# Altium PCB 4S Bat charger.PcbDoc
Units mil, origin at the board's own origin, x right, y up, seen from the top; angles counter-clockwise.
Board outline 3472.44 x 2830.71 mil, 2 copper layers (Top Layer, Bottom Layer); 157 components, 75 nets, 480 pads, 93 vias.
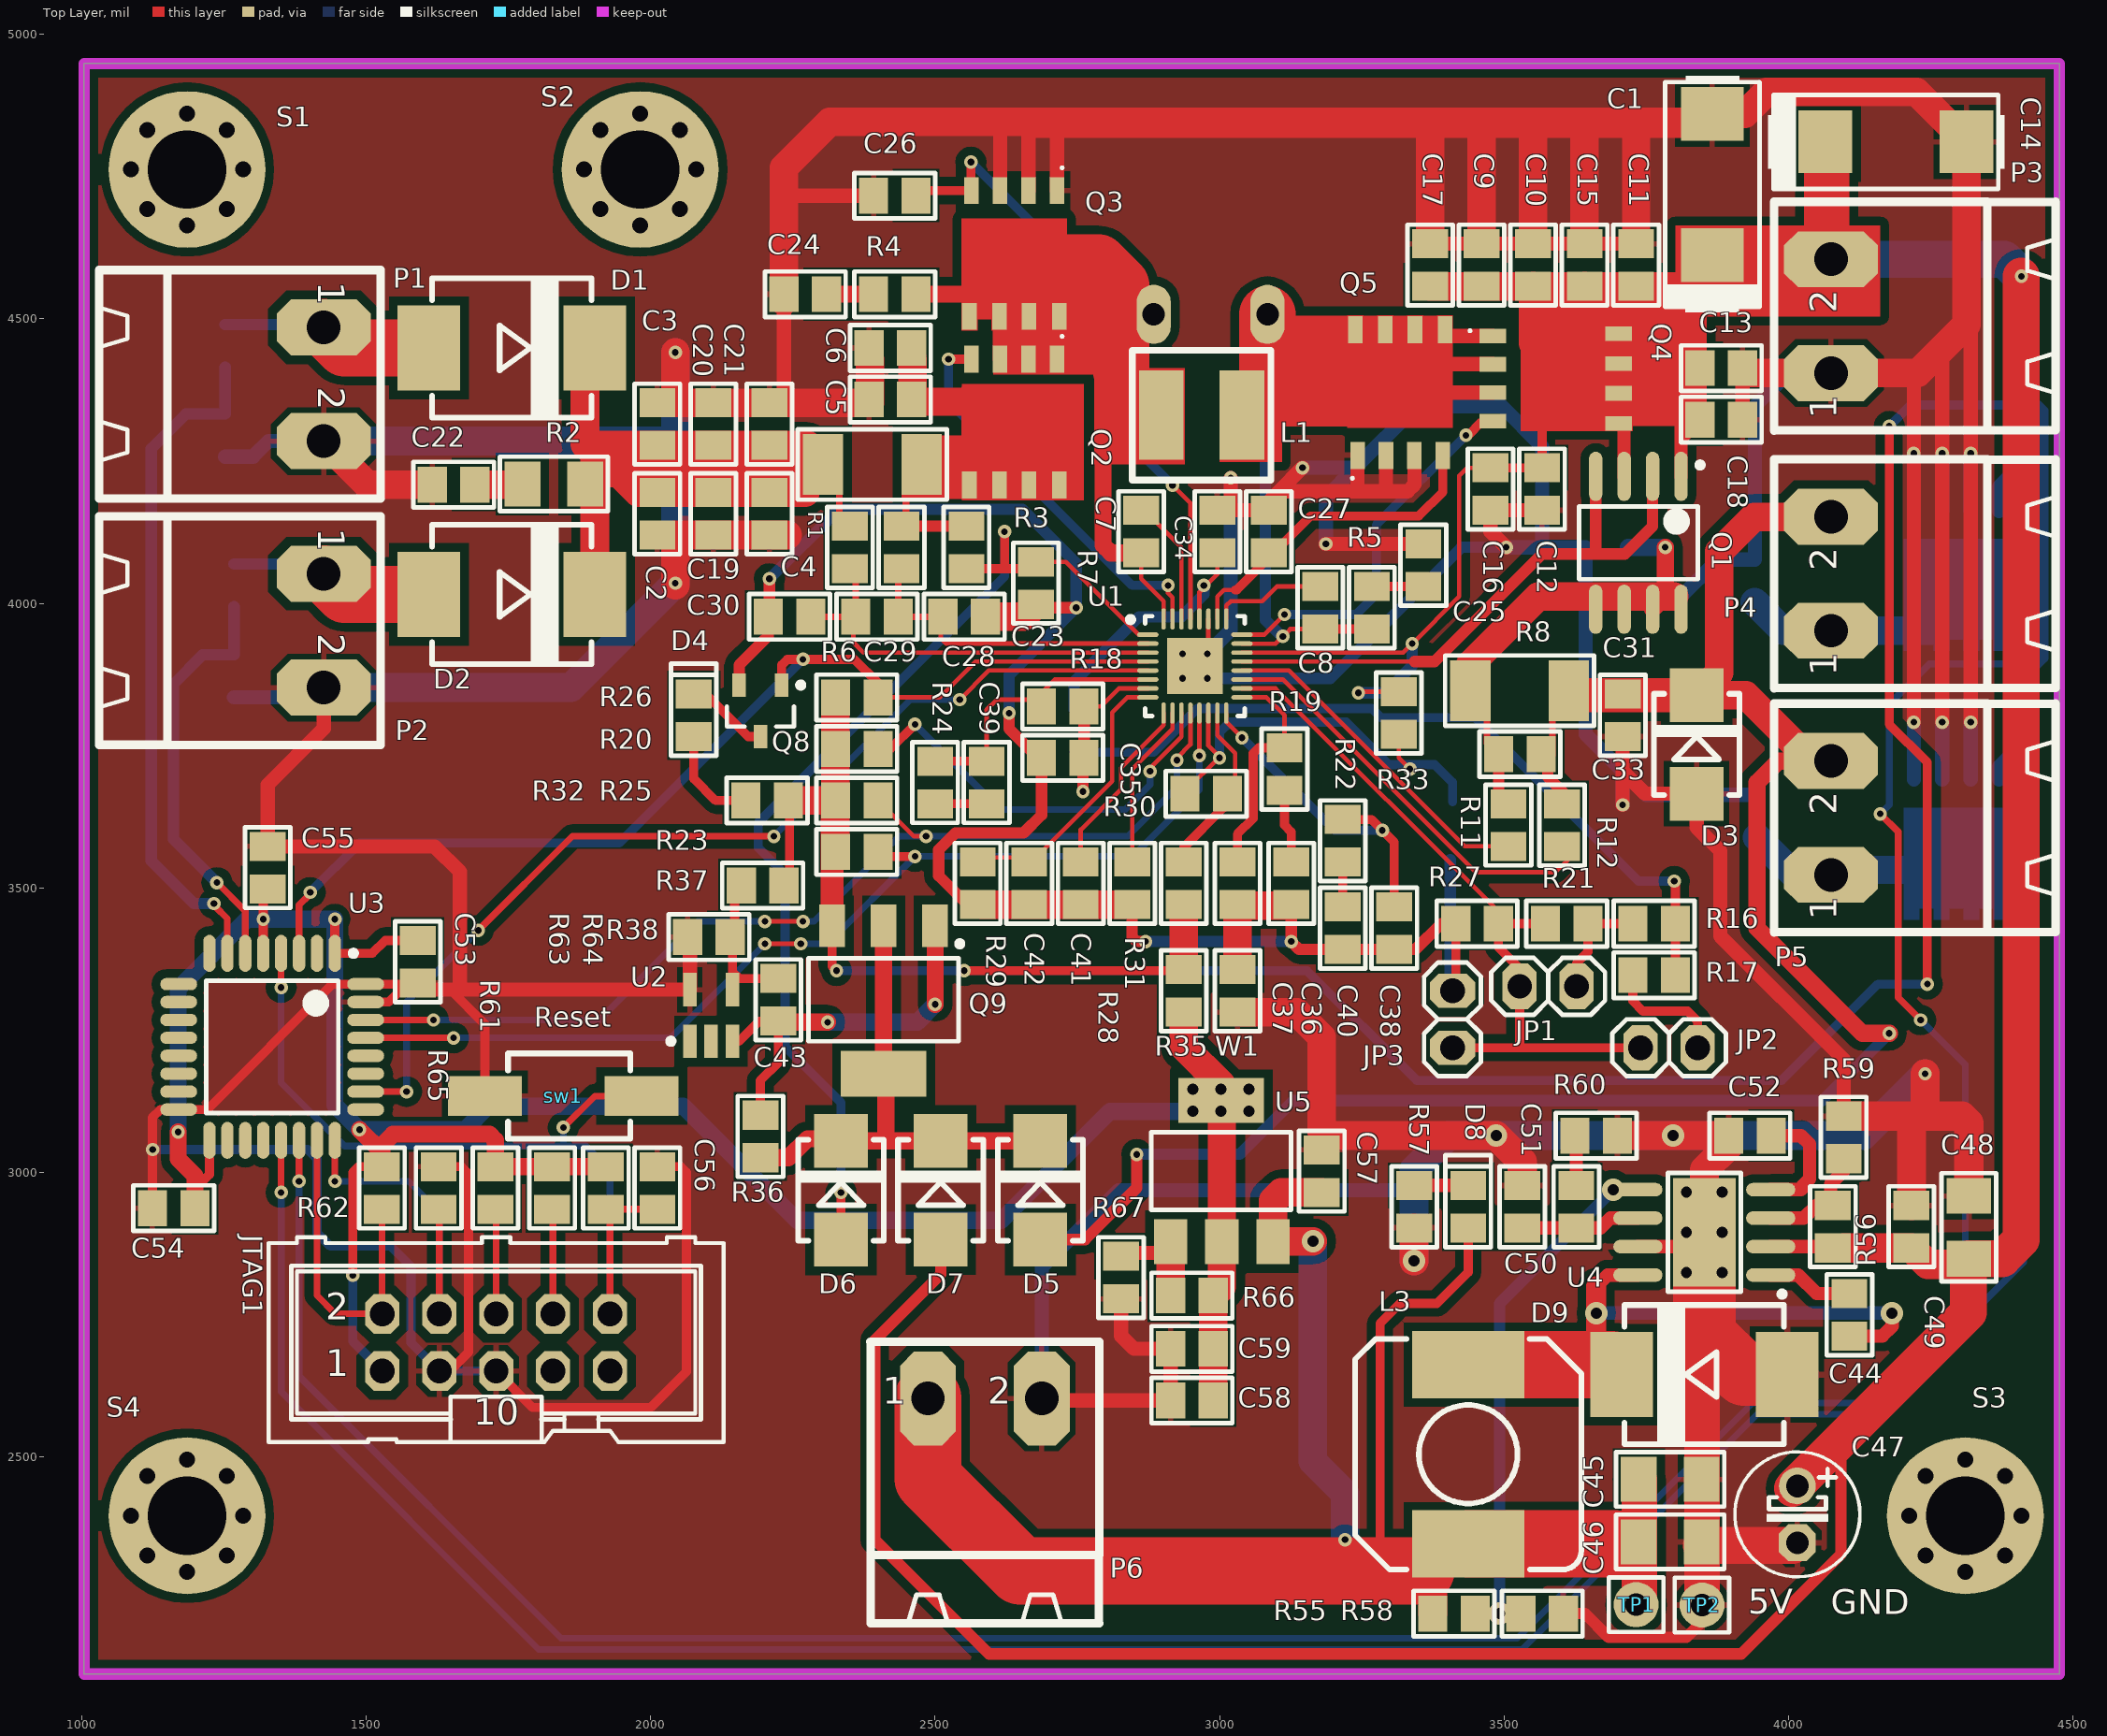
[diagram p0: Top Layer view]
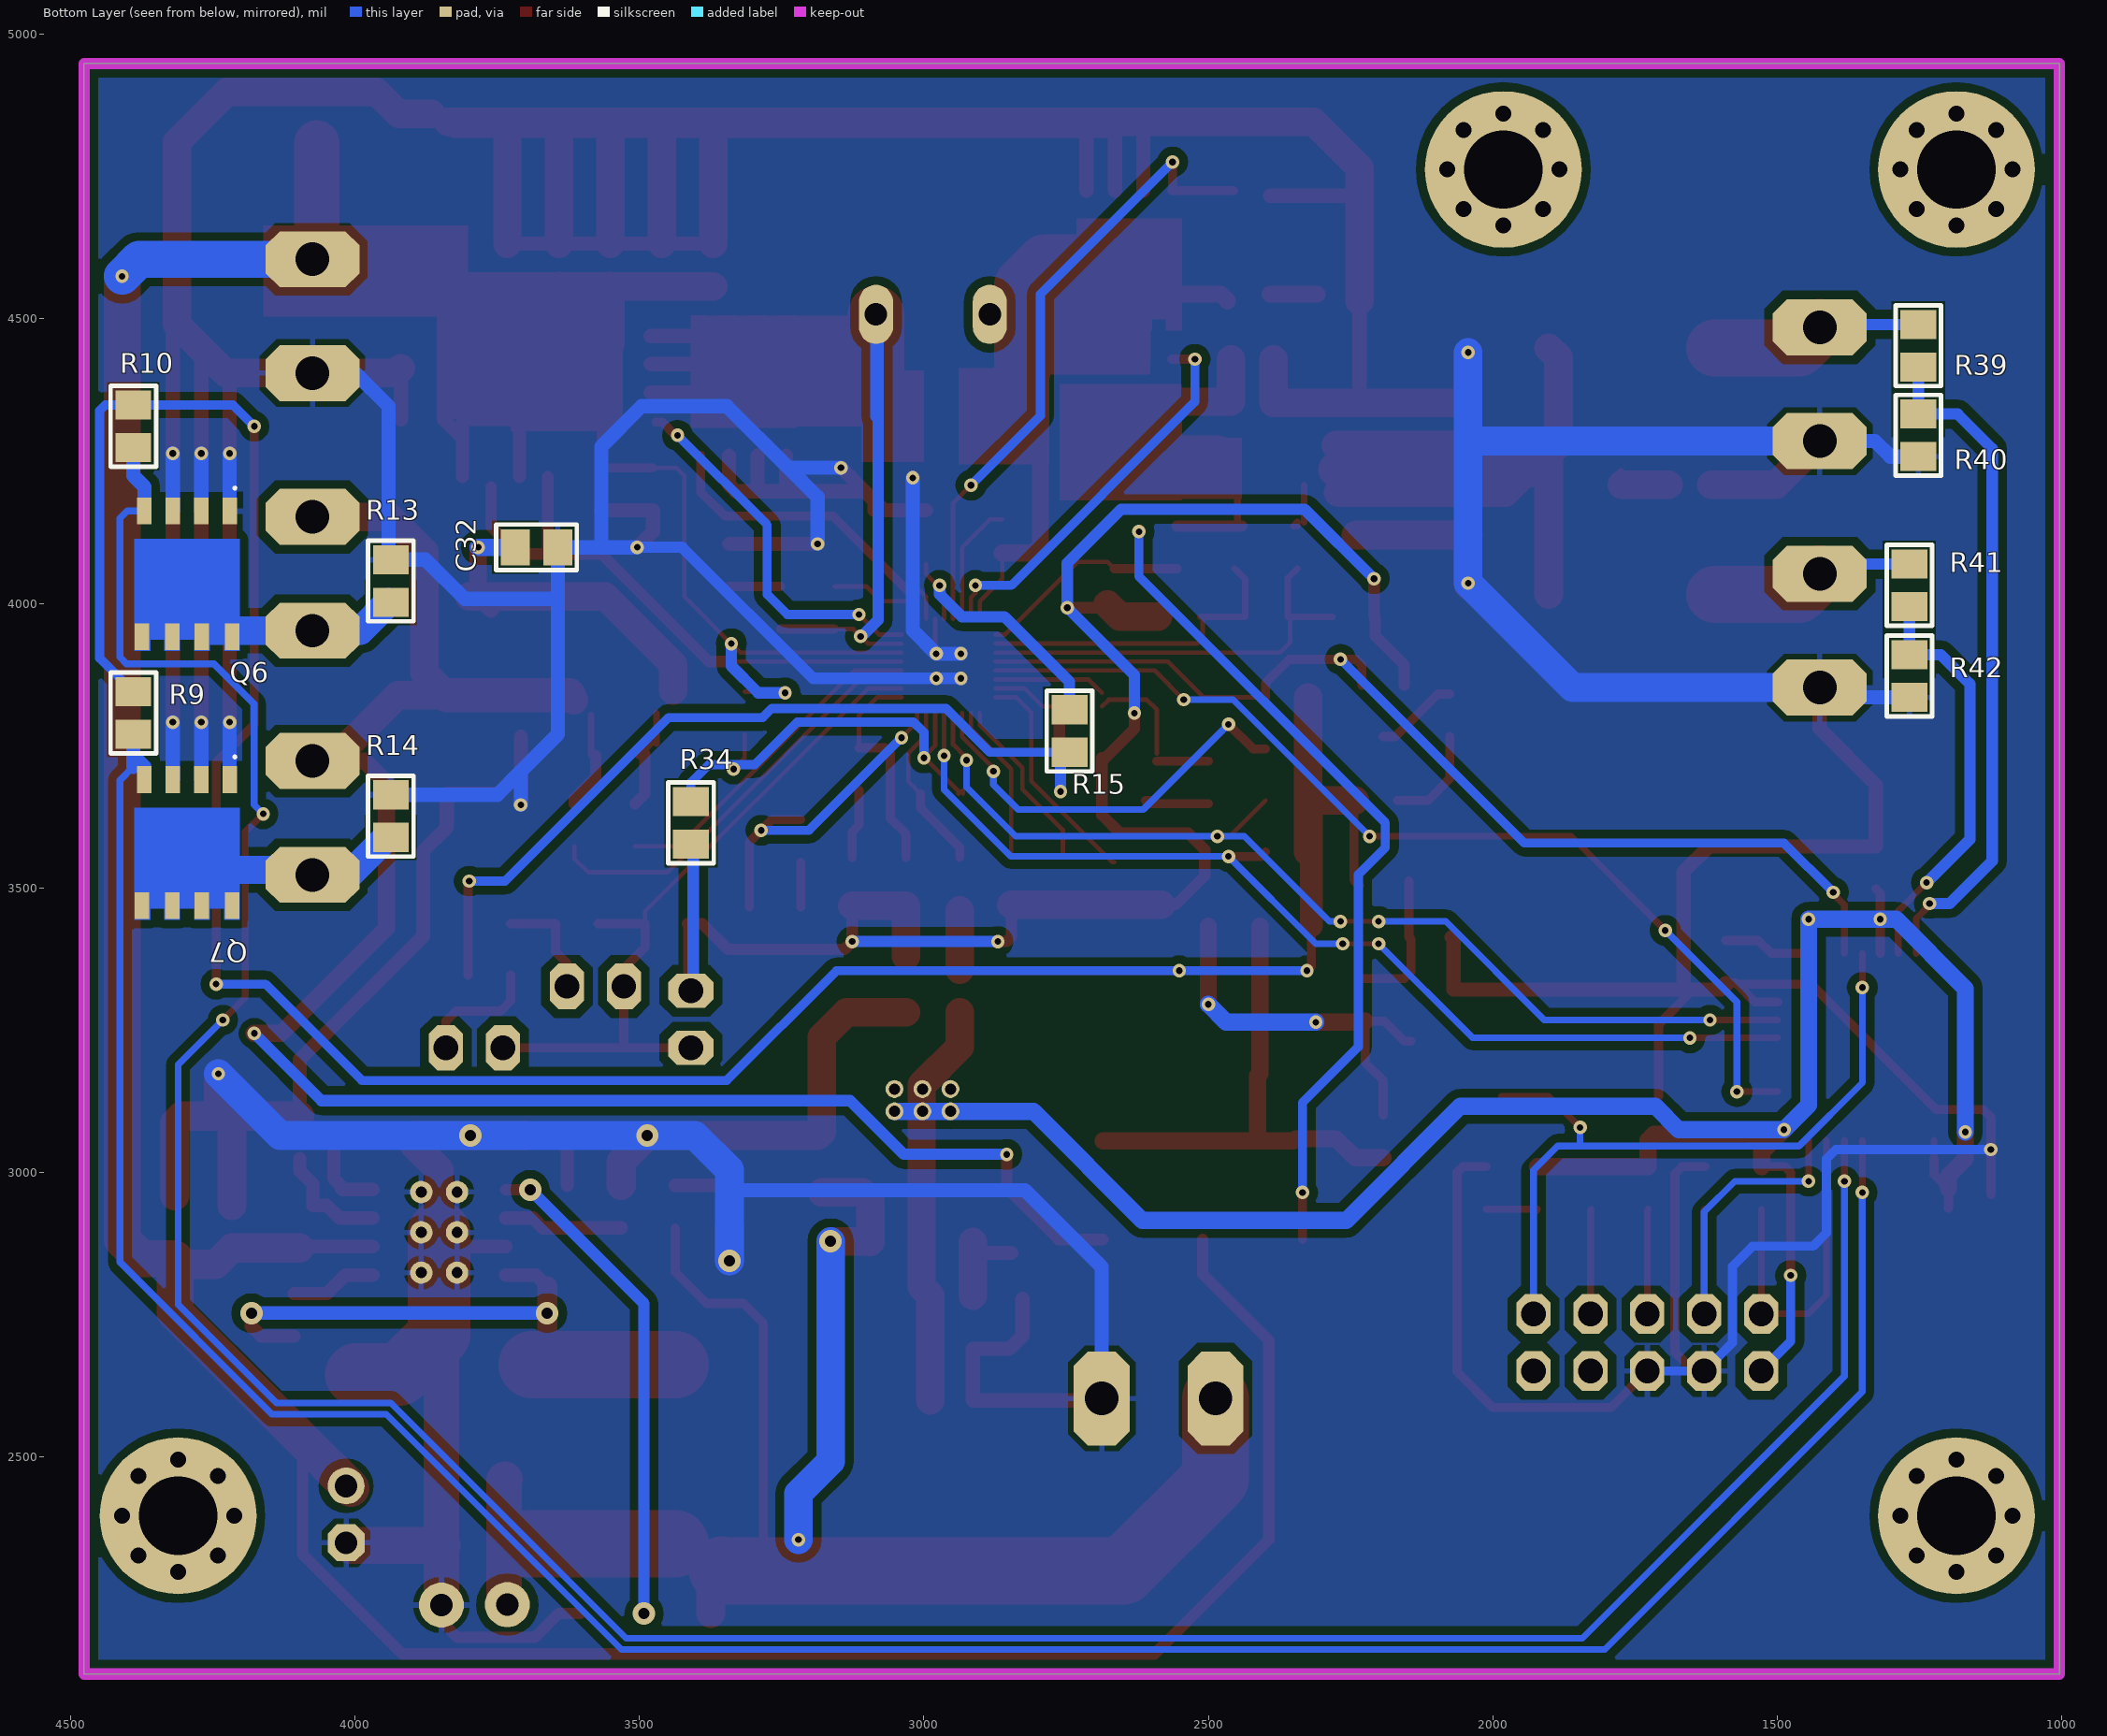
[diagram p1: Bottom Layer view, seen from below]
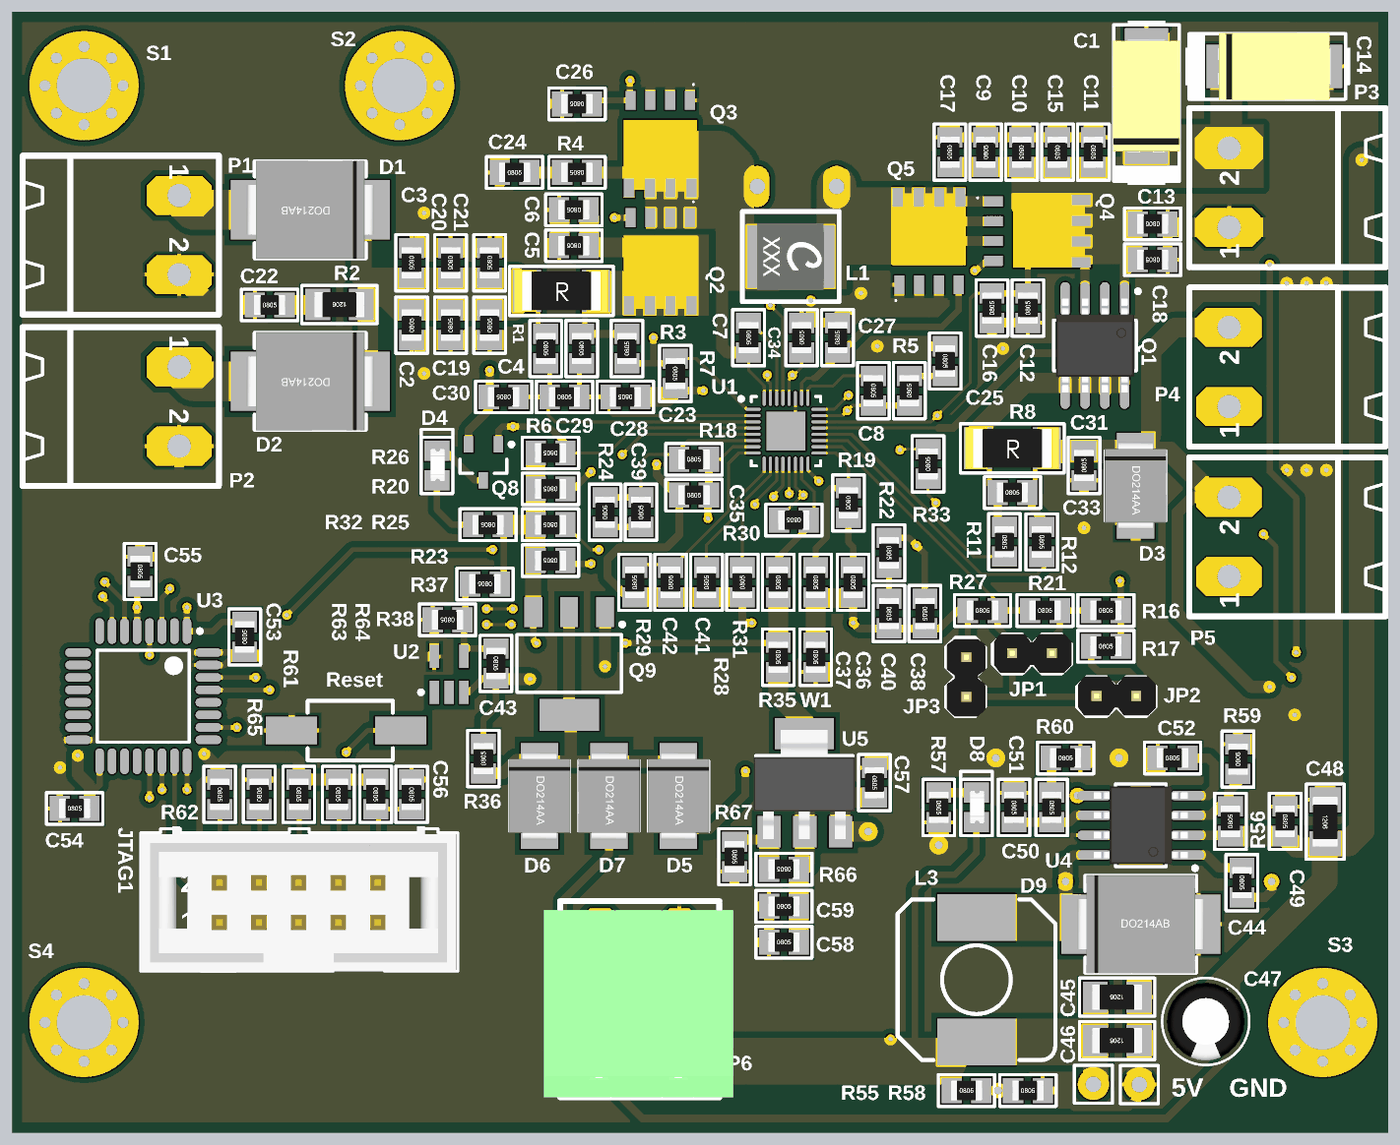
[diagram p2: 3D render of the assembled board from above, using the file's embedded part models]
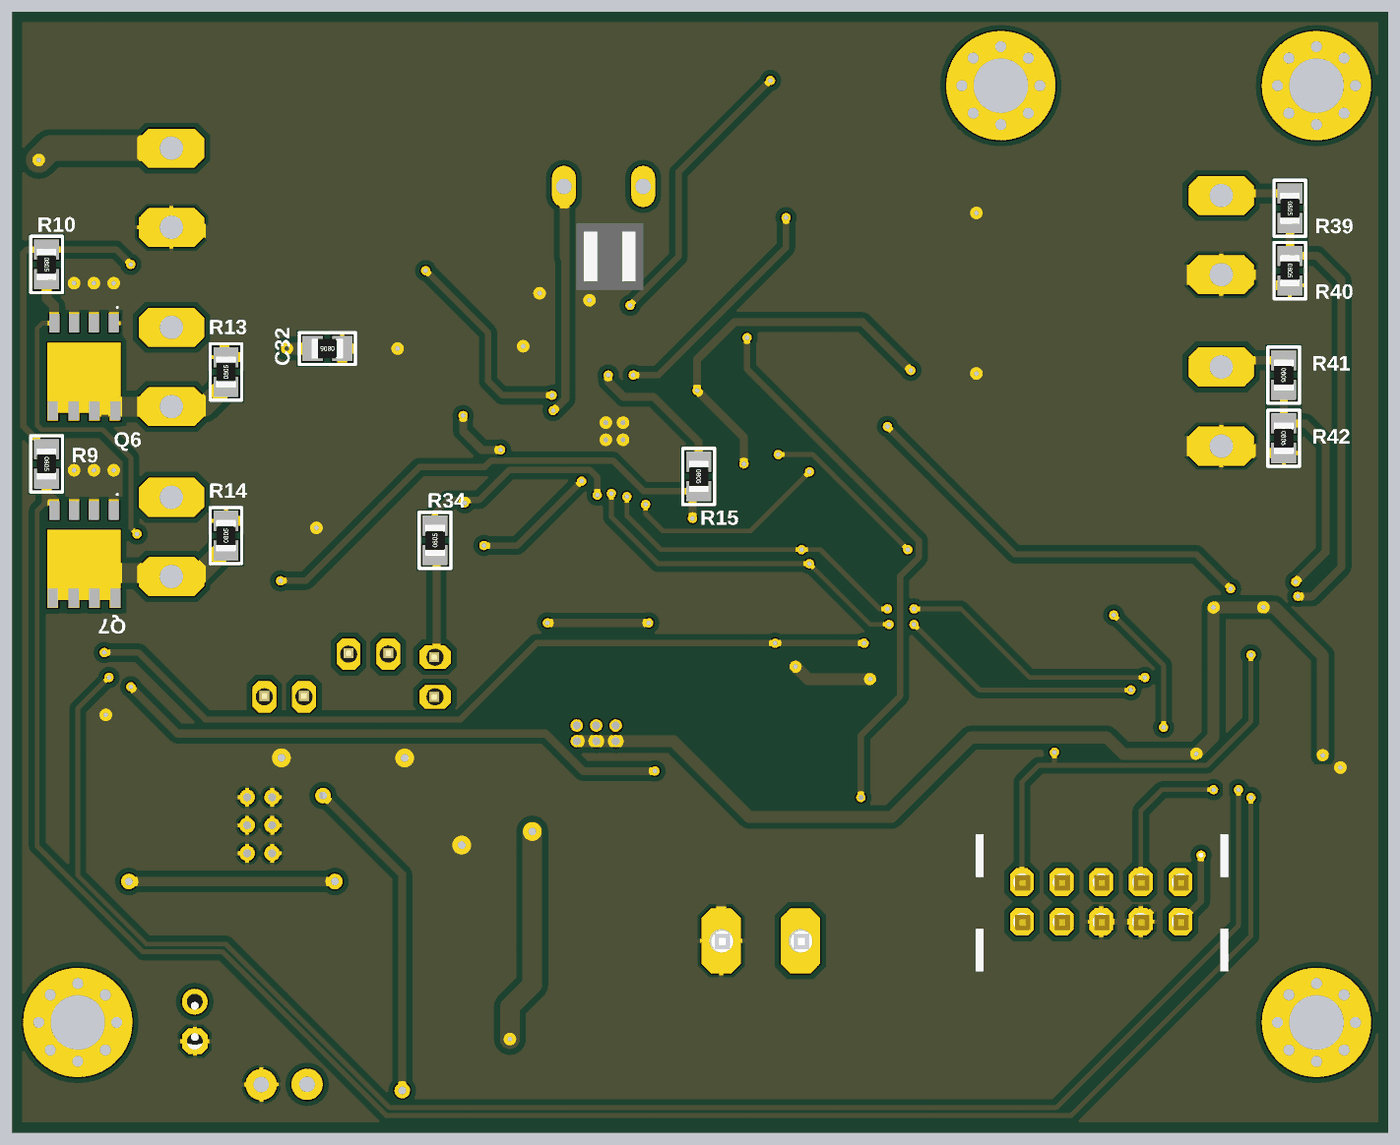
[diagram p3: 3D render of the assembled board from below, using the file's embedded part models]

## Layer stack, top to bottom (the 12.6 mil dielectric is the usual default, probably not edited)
Top Solder: solder mask 0.4, Solder Resist, Dk 3.5
Top Layer: signal copper 1.4
Dielectric 1: dielectric 12.6, FR-4, Dk 4.8
Bottom Layer: signal copper 1.4
Bottom Solder: solder mask 0.4, Solder Resist, Dk 3.5

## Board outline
1003.94,2118.11 4476.38,2118.11 4476.38,4948.82 1003.94,4948.82

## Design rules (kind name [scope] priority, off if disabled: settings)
Clearance Clearance_1 [InNamedPolygon('Bot_PGND') Or  InNamedPolygon('Top_PGND')] p1: gap=15 ignorepadtopadclearanceinfootprint=FALSE
Clearance [All] p2: gap=7.8 ignorepadtopadclearanceinfootprint=FALSE
HoleSize [All] p1: absolutevalues=TRUE maxlimit=196.85 minlimit=1 maxpercent=80.000 minpercent=20.000
MinimumSolderMaskSliver [All] p1: minsoldermaskwidth=4
PolygonConnect PolygonConnect_ViA [All vs IsVia] p1: connectstyle=Direct reliefconductorwidth=10 reliefentries=4 polygonreliefangle="90 Angle" airgapwidth=10
PolygonConnect [All] p2: connectstyle=Relief reliefconductorwidth=10 reliefentries=4 polygonreliefangle="90 Angle" airgapwidth=10
RoutingVias [All] p1: holewidth=11.81 width=23.62 viastyle="Through Hole" minholewidth=11.81 minwidth=23.62 maxholewidth=19.68 maxwidth=39.37
SilkToSilkClearance [All] p1: silktosilkclearance=4
SilkToSolderMaskClearance [IsPad] p1: minsilkscreentomaskgap=4 clearancetoexposedcopper=TRUE
SolderMaskExpansion [All] p1: expansion=4
Width [All] p1: maxlimit=200 minlimit=7 preferedwidth=11.81
26 further rules are at their usual default settings.

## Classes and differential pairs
net class VADC_[7..0]: VADC_0 VADC_1
component class "U_[02] MCU": C44 C45 C46 C47 C48 C49 C50 C51 C52 C53 C54 C55 C56 C57 C58 C59 D8 D9 JTAG1 L3 P6 R39 R40 R41 R42 R55 R56 R57 R58 R59 R60 R61 R62 R63 R64 R65 R66 R67 sw1 TP1 TP2 U3 U4 U5
component class "[01] Main": C1 C2 C3 C4 C5 C6 C7 C8 C9 C10 C11 C12 C13 C14 C15 C16 C17 C18 C19 C20 C21 C22 C23 C24 C25 C26 C27 C28 C29 C30 C31 C32 C33 C34 C35 C36 C37 C38 C39 C40 C41 C42 C43 D1 D2 D3 D4 D5 D6 D7 JP1 JP2 JP3 L1 P1 P2 P3 P4 P5 Q1 Q2 Q3 Q4 Q5 Q6 Q7 Q8 Q9 R1 R2 R3 R4 R5 R6 R7 R8 R9 R10 R11 R12 R13 R14 R15 R16 R17 R18 R19 R20 R21 R22 R23 R24 R25 R26 R27 R28 R29 R30 R31 R32 R33 R34 R35 R36 R37 R38 S1 S2 S3 S4 U1 U2 W1

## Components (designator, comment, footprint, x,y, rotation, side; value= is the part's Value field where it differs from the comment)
C1 "47u" MY_SMC_D 3866.14,4736.22 r90 top
C2 "10uF" MY_0805 2011.81,4157.48 r90 top
C3 "10uF" MY_0805 2011.81,4314.96 r270 top
C4 "10uF" MY_0805 2208.66,4157.48 r90 top
C5 "10nF" MY_0805 2421.26,4358.27 r180 top
C6 "1nF" MY_0805 2421.26,4448.82 r180 top
C7 "47nF" MY_0805 2862.2,4125.98 r270 top
C8 "47nF" MY_0805 3177.17,3992.13 r270 top
C9 "10nF" MY_0805 3460.63,4594.49 r90 top
C10 "10uF" MY_0805 3551.18,4594.49 r270 top
C11 "10uF" MY_0805 3732.28,4594.49 r270 top
C12 "10uF" MY_0805 3566.93,4200.79 r90 top
C13 "DNP" MY_0805 3881.89,4413.39 r180 top
C14 "DNP" MY_SMC_D 4188.98,4811.02 r0 top
C15 "10uF" MY_0805 3641.73,4594.49 r270 top
C16 "10uF" MY_0805 3476.38,4200.79 r90 top
C17 "10uF" MY_0805 3370.08,4594.49 r270 top
C18 "DNP" MY_0805 3881.89,4322.83 r180 top
C19 "10uF" MY_0805 2110.24,4157.48 r90 top
C20 "10uF" MY_0805 2110.24,4314.96 r270 top
C21 "10uF" MY_0805 2208.66,4314.96 r270 top
C22 "1uF" MY_0805 1653.54,4208.66 r0 top
C23 "470nF" MY_0805 2677.17,4035.43 r270 top
C24 "DNP" MY_0805 2271.65,4543.31 r0 top
C25 "DNP" MY_0805 3358.27,4066.93 r270 top
C26 "150pF" MY_0805 2429.13,4716.54 r180 top
C27 "150pF" MY_0805 3086.61,4125.98 r90 top
C28 "15nF" MY_0805 2551.18,3976.38 r180 top
C29 "DNP" MY_0805 2397.64,3976.38 r0 top
C30 "15nF" MY_0805 2244.09,3976.38 r180 top
C31 "10uF" MY_0805 3708.66,3803.15 r90 top
C32 "1uF" MY_0805 3681.1,4098.43 r0 bottom
C33 "100nF" MY_0805 3528,3735 r0 top
C34 "2.2uF" MY_0805 2996.06,4125.98 r90 top
C35 "1uF" MY_0805 2724.41,3728.35 r0 top
C36 "680pF" MY_0805 3125.98,3507.87 r270 top
C37 "15pF" MY_0805 3031.5,3507.87 r270 top
C38 "33pF" MY_0805 3307.09,3429.13 r270 top
C39 "100pF" MY_0805 2590.55,3685.04 r90 top
C40 "1.8nF" MY_0805 3216.54,3429.13 r270 top
C41 "100pF" MY_0805 2755.91,3507.87 r90 top
C42 "100pF" MY_0805 2665.35,3507.87 r90 top
C43 "100nF" MY_0805 2224.41,3303.15 r270 top
C44 "100nF" MY_0805 4107.13,2749.41 r270 top
C45 "47uF" MY_1206 3793.13,2459.41 r180 top
C46 "47uF" MY_1206 3793.13,2349.41 r180 top
C47 "100u" MY_E2.5-6mm 4015.75,2398.82 r270 top
C48 "10uF" MY_1206 4318.13,2904.41 r270 top
C49 "10nF" MY_0805 4216.13,2904.41 r270 top
C50 "4.7nF" MY_0805 3627.13,2939.41 r270 top
C51 "39pF" MY_0805 3532.13,2939.41 r270 top
C52 "10nF" MY_0805 3932.13,3064.41 r0 top
C53 "100nF" MY_0805 1590.55,3370.08 r90 top
C54 "100nF" MY_0805 1161.42,2937.01 r0 top
C55 "100nF" MY_0805 1326.77,3535.43 r270 top
C56 "100nF" MY_0805 2011.81,2972.44 r270 top
C57 "10uF" MY_0805 3179.75,3001.97 r270 top
C58 "10uF" MY_0805 2951.41,2599.15 r0 top
C59 "100nF" MY_0805 2951.41,2689.7 r0 top
D1 "CDBC5100" MY_SMC 1755.91,4448.82 r180 top
D2 "CDBC5100" MY_SMC 1755.91,4015.75 r180 top
D3 "DNP" MY_SMB 3838.58,3751.97 r270 top
D4 "LED" MY_LED_0805 2078.74,3803.15 r270 top
D5 "SS34" MY_SMB 2685.04,2968.5 r270 top
D6 "SS34" MY_SMB 2334.65,2968.5 r270 top
D7 "SS34" MY_SMB 2509.84,2968.5 r270 top
D8 "LED" MY_LED_0805 3440.13,2939.41 r270 top
D9 "CDBC5100-G" MY_SMC 3852.13,2644.41 r0 top
JP1 "Header 2" My_1X02 3527.56,3326.77 r180 top
JP2 "Header 2" My_1X02 3740.16,3218.9 r180 top
JP3 "Header 2" My_1X02 3409.45,3318.9 r90 top
JTAG1 "Header 5X2" MY_2X05_BOX 1728.35,2700.79 r0 top
L1 "2.2uH" L5mm 2968.5,4330.71 r270 top
L3 "NR10050T100M" MY_DR1030 3437.13,2504.41 r180 top value=10uH
P1 "Header 2" MY_MSTBA2 1295.28,4370.08 r270 top
P2 "Header 2" MY_MSTBA2 1295.28,3937.01 r270 top
P3 "Header 2" MY_MSTBA2 4204.72,4519.69 r90 top
P4 "Header 2" MY_MSTBA2 4204.72,4066.93 r90 top
P5 "Header 2" MY_MSTBA2 4204.72,3637.8 r90 top
P6 "Header 2" MY_MSTBA2 2602.36,2472.44 r0 top
Q1 "AO4805" My_SOIC_P8 3736.22,4106.3 r270 top
Q2 "BSC100N06LS3 G" INF-PG-TDSON-8-1_V 2639.17,4317.91 r180 top
Q3 "BSC100N06LS3 G" INF-PG-TDSON-8-1_V 2639.17,4614.17 r180 top
Q4 "BSC100N06LS3 G" INF-PG-TDSON-8-1_V 3591.54,4395.08 r270 top
Q5 "BSC100N06LS3 G" INF-PG-TDSON-8-1_V 3317.52,4371.06 r0 top
Q6 "BSC100N06LS3 G" INF-PG-TDSON-8-1_V 4295.28,4051.18 r0 bottom
Q7 "BSC100N06LS3 G" INF-PG-TDSON-8-1_V 4295.28,3578.74 r0 bottom
Q8 "2N7002" INF-PG-SOT23_N 2192.91,3811.02 r270 top
Q9 "BCP56-16" INF-SOT223_SC-73_N 2409.45,3303.15 r270 top
R1 "0.01" MY_2010 2389.76,4244.09 r0 top
R2 "2.2" MY_1206 1830.71,4208.66 r180 top
R3 "1" MY_0805 2555.12,4098.43 r90 top
R4 "DNP" MY_0805 2429.13,4543.31 r180 top
R5 "DNP" MY_0805 3267.72,3992.13 r90 top
R6 "10" MY_0805 2350.39,4098.43 r270 top
R7 "10" MY_0805 2440.94,4098.43 r270 top
R8 "0.01" MY_2010 3527.56,3846.46 r0 top
R9 "1K" MY_0805 4389.76,3807.09 r270 bottom
R10 "NC" MY_0805 4389.76,4311.02 r270 bottom
R11 "10" MY_0805 3507.87,3610.24 r270 top
R12 "10" MY_0805 3602,3610 r270 top
R13 "NC" MY_0805 3937.01,4039.37 r90 bottom
R14 "NC" MY_0805 3937.01,3625.98 r90 bottom
R15 "10" MY_0805 2744.09,3775.59 r270 bottom
R16 "120K" MY_0805 3763.78,3437.01 r0 top
R17 "64.9K" MY_0805 3763.78,3346.46 r0 top
R18 "383K" MY_0805 2724.41,3818.9 r0 top
R19 "10K" MY_0805 3114.17,3708.66 r270 top
R20 "10K" MY_0805 2362.2,3744.09 r180 top
R21 "280K" MY_0805 3610.24,3437.01 r0 top
R22 "40.2K" MY_0805 3216.54,3582.68 r270 top
R23 "10K" MY_0805 2362.2,3562.99 r180 top
R24 "220K" MY_0805 2500,3685.04 r90 top
R25 "10K" MY_0805 2362.2,3653.54 r180 top
R26 "10K" MY_0805 2362.2,3834.65 r180 top
R27 "100K" MY_0805 3452.76,3437.01 r0 top
R28 "10K" MY_0805 2937.01,3507.87 r270 top
R29 "137K" MY_0805 2574.8,3507.87 r90 top
R30 "2M" MY_0805 2976.38,3665.35 r180 top
R31 "30.1K" MY_0805 2846.46,3507.87 r90 top
R32 "226" MY_0805 2204.72,3653.54 r180 top
R33 "DNP" MY_0805 3314.96,3807.09 r90 top
R34 "300K" MY_0805 3409.45,3614.17 r90 bottom
R35 "NC" MY_0805 2937.01,3318.9 r270 top
R36 "10K" MY_0805 2192.91,3062.99 r90 top
R37 "2.4K" MY_0805 2196.85,3503.94 r180 top
R38 "7.5K" MY_0805 2102.36,3413.39 r180 top
R39 "NC" MY_0805 1251.97,4452.76 r270 bottom
R40 "1K" MY_0805 1251.97,4295.28 r270 bottom
R41 "NC" MY_0805 1267.72,4031.5 r270 bottom
R42 "1K" MY_0805 1267.72,3872.05 r270 bottom
R55 "5.23K" MY_0805 3412.13,2224.41 r0 top
R56 "1.8K" MY_0805 4078.13,2904.41 r90 top
R57 "330" MY_0805 3342.13,2939.41 r270 top
R58 "1K" MY_0805 3567.13,2224.41 r0 top
R59 "390" MY_0805 4097.13,3061.41 r90 top
R60 "49.9K" MY_0805 3662.13,3064.41 r0 top
R61 "10K" MY_0805 1727.03,2972.44 r270 top
R62 "10K" MY_0805 1527.56,2972.44 r270 top
R63 "10K" MY_0805 1826.77,2972.44 r270 top
R64 "10K" MY_0805 1921.26,2972.44 r270 top
R65 "10K" MY_0805 1627.3,2972.44 r90 top
R66 "120" MY_0805 2951.41,2783.46 r180 top
R67 "200" MY_0805 2826.77,2814.96 r270 top
S1 "Screw" MY_PAD_3MM 1185.04,4762.51 r0 top net-tie
S2 "Screw" MY_PAD_3MM 1981.58,4762.51 r0 top net-tie
S3 "Screw" MY_PAD_3MM 4311.02,2396.36 r0 top net-tie
S4 "Screw" MY_PAD_3MM 1185.04,2396.36 r0 top net-tie
sw1 "Reset" MY_PB-SMD 1984.25,3133.86 r180 top
TP1 "5V" MY_TestPin 3732.28,2240.16 r270 top
TP2 "GND" MY_TestPin 3848.13,2239.41 r270 top
U1 "BQ25703A" QFN40P400X400X80_HS-33N 2956.69,3889.76 r0 top
U2 "TL431ACDBVR" TI-DBV5_N 2106.3,3275.59 r90 top
U3 "STM32F030K6T6" STM-LQFP32_N 1334.65,3220.47 r270 top
U4 "TPS54331" My_SOIC_P8_powerPad 3852.13,2894.41 r180 top
U5 "LM1117" MY_SOT223 3002.59,3004.66 r0 top
W1 "Jumper" MY_0805 3031.5,3318.9 r270 top

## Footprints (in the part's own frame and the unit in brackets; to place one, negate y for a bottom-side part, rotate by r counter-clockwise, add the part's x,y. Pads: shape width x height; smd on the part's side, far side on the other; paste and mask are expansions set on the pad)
INF-PG-SOT23_N [mm] "SOT23, 3-Leads, Body 2.9x1.3mm, Pitch 0.95mm, IPC Medium Density"
  rect 1.05x0.6 smd: 1(-1.15,0.95) 2(-1.15,-0.95) 3(1.15,0)
  silkscreen extent -1.27,-1.5 0.7,1.93, body extent -0.7,-1.5 0.7,1.5, height 1.1
INF-PG-TDSON-8-1_V [mm] "TDSON, 8-Leads, Body 6.15x5.15mm, Pitch 1.27mm"
  rect 0.65x1.2 smd: 1(-1.905,-2.825) 2(-0.635,-2.825) 3(0.635,-2.825) 4(1.905,-2.825) 5(2.007,2.794) 6(0.66,2.794) 7(-0.66,2.794) 8(-2.007,2.794)
  Top Layer region: 0.315,2.925 1.015,2.925 1.015,3.425 0.315,3.425
  Top Layer region: -1.015,2.925 -0.315,2.925 -0.315,3.425 -1.015,3.425
  Top Layer region: 1.65,2.925 2.35,2.925 2.35,3.425 1.65,3.425
  Top Layer region: -2.35,2.925 -1.65,2.925 -1.65,3.425 -2.35,3.425
  Top Layer region: -2.35,2.925 -2.35,-1.575 2.35,-1.575 2.35,2.925
  silkscreen extent -2.23,-3.94 -2.03,-3.74, body extent -2.58,-3.08 2.58,3.08, height 1
INF-SOT223_SC-73_N [mm] "SOT223, 4-Leads, Body 6.5x3.5mm, Pitch 2.3mm, IPC Medium Density"
  rect 1.905x1.143 smd: 1(-3.3,2.3) 2(-3.3,0) 3(-3.3,-2.3)
  rect 2.032x3.81 smd: 4(3.3,0)
  silkscreen extent -2.62,-3.35 1.85,3.53, body extent -1.85,-3.35 1.85,3.35, height 1.8
L5mm [mm]
  rect 4x2 smd: 1(0,-1.8) 2(0,1.8)
  Top Layer pour cut-out: -3,3.1 -3,-3.1 3,-3.1 3,3.1
  silkscreen extent -2.9,-3.1 2.9,3.1, body extent -2.15,-2.15 2.15,2.15, height 1.05
My_1X02 [mil]
  oct 60x80 hole 43.31: 1(-100,0) 2(0,0)
  silkscreen extent -150,-50 50,50, body extent -150,-51 46,47, height 323
MY_2X05_BOX [mil]
  oct 60x70 hole 43.31: 1(-200,-50) 2(-200,50) 3(-100,-50) 4(-100,50) 5(0,-50) 6(0,50) 7(100,-50) 8(100,50) 9(200,-50) 10(200,50)
  silkscreen extent -400,-175 400,185, body extent -400,-179 396,191, height 347
MY_0805 [mm]
  rect 1.3x1.6 smd: 1(-0.95,0) 2(0.95,0)
  silkscreen extent -1.8,-1.02 1.8,1.02, body extent -1,-0.62 1,0.63, height 0.59
MY_1206 [mm]
  rect 1.6x2 smd: 1(-1.375,-0.025) 2(1.425,-0.025)
  silkscreen extent -2.39,-1.24 2.44,1.19, body extent -1.57,-0.83 1.63,0.77, height 0.59
MY_2010 [mm]
  rect 1.8x2.7 smd: 1(-2.2,0) 2(2.2,0)
  silkscreen extent -3.33,-1.57 3.33,1.57, body extent -3,-1.35 3,1.35, height 0.62
MY_DR1030 [mm]
  rect 5x3 smd: 1(0,-4) 2(0,4)
  silkscreen extent -5.05,-5.15 5.05,5.15
MY_E2.5-6mm [mil]
  round 65 hole 40: +(-50,0)
  oct 65x65 hole 40: -(50,0)
  silkscreen extent -110,-110 110,110, body extent -98,-98 98,98, height 277
MY_LED_0805 [mm]
  rect 1.3x1.6 smd: A(0.95,-0.076) K(-0.95,-0.076)
  silkscreen extent -2.31,-1.09 1.8,0.94, body extent -1.06,-0.48 1.01,0.42, height 0.86
MY_MSTBA2 [mil]
  oct 98.43x165.01 hole 59.06: 1(-115,130) 2(85,130)
  silkscreen extent -216,-265 186,230
MY_PAD_3MM [mil]
  round 50 hole 28: 0(-98.43,0) 0(-69.6,-69.6) 0(-69.6,69.6) 0(0,-98.43) 0(0,98.43) 0(69.6,-69.6) 0(69.6,69.6) 0(98.43,0)
  round 275.59 hole 137.8: 0(0,0)
MY_PB-SMD [mil] "Switch; 2 Leads"
  rect 130x70 smd: 1(0,0) 2(275.59,0)
  silkscreen extent 20,-75 235,75
MY_SMB [mm]
  rect 2.4x2.4 smd: A(2.2,0) K(-2.2,0)
  silkscreen extent -2.26,-1.91 2.26,1.91, body extent -2.79,-1.97 2.79,1.98, height 2.62
MY_SMC [mm]
  rect 2.8x3.8 smd: A(3.7,0) K(-3.7,0)
  silkscreen extent -3.56,-3.1 3.56,3.1, body extent -4.06,-3.15 4.06,3.15, height 2.62
MY_SMC_D [mm]
  rect 2.4x2.8 smd: +(-3.15,0) -(3.15,0)
  silkscreen extent -5.71,-2.11 4.85,2.1, body extent -3.65,-2.15 3.65,2.15, height 2.83
My_SOIC_P8 [mm]
  oval 2.2x0.6 smd: 1(-2.965,1.905) 2(-2.965,0.635) 3(-2.965,-0.635) 4(-2.965,-1.905) 5(2.965,-1.905) 6(2.965,-0.635) 7(2.965,0.635) 8(2.965,1.905)
  silkscreen extent -3.6,-2.65 1.63,2.88, body extent -3.01,-2.5 3.01,2.5, height 1.75
My_SOIC_P8_powerPad [mm]
  oval 2.2x0.6 smd: 1(-2.965,1.905) 2(-2.965,0.635) 3(-2.965,-0.635) 4(-2.965,-1.905) 5(2.965,-1.905) 6(2.965,-0.635) 7(2.965,0.635) 8(2.965,1.905)
  round 1 hole 0.5: 7(-0.8,1.8) 7(-0.8,0) 7(-0.8,-1.8) 7(0.8,1.8) 7(0.8,0) 7(0.8,-1.8)
  rect 2.8x4.85 smd: 7(0,0)
  silkscreen extent -3.6,-2.65 1.63,2.88, body extent -3.01,-2.5 3.01,2.5, height 1.75
MY_SOT223 [mm]
  rect 1.499x2.007 smd: 1(-2.252,-3.218) 2(0.034,-3.218) 3(2.32,-3.218)
  round 0.8 hole 0.5: 2(-1.25,2.6) 2(-1.25,3.6) 2(0,2.6) 2(0,3.6) 2(1.25,2.6) 2(1.25,3.6)
  rect 3.81x2.007 smd: 2(0.009,3.081)
  silkscreen extent -3.12,-1.8 3.13,1.66, body extent -3.25,-3.68 3.25,3.32, height 1.67
MY_TestPin [mil]
  round 79 hole 39.37: 1(0,0)
  silkscreen extent -48,-48 48,48
QFN40P400X400X80_HS-33N [mm] "QFN, 32-Leads, Body 4.00x4.00mm, Pitch 0.40mm, Thermal Pad 2.50x2.50mm, IPC Medium Density"
  oval 0.95x0.2 smd: 1(-2.1,1.4) 2(-2.1,1) 3(-2.1,0.6) 4(-2.1,0.2) 5(-2.1,-0.2) 6(-2.1,-0.6) 7(-2.1,-1) 8(-2.1,-1.4) 17(2.1,-1.4) 18(2.1,-1) 19(2.1,-0.6) 20(2.1,-0.2) 21(2.1,0.2) 22(2.1,0.6) 23(2.1,1) 24(2.1,1.4)
  oval 0.2x0.95 smd: 9(-1.4,-2.1) 10(-1,-2.1) 11(-0.6,-2.1) 12(-0.2,-2.1) 13(0.2,-2.1) 14(0.6,-2.1) 15(1,-2.1) 16(1.4,-2.1) 25(1.4,2.1) 26(1,2.1) 27(0.6,2.1) 28(0.2,2.1) 29(-0.2,2.1) 30(-0.6,2.1) 31(-1,2.1) 32(-1.4,2.1)
  rect 2.5x2.5 smd: 33(0,0)
  silkscreen extent -3,-2.23 2.23,2.22, body extent -2.07,-2.08 2.08,2.07, height 0.8
STM-LQFP32_N [mm] "QFP, 32-Leads, Body 7x7mm, Pitch 0.8mm, IPC Medium Density"
  oval 1.65x0.55 smd: 1(-4.175,2.8) 2(-4.175,2) 3(-4.175,1.2) 4(-4.175,0.4) 5(-4.175,-0.4) 6(-4.175,-1.2) 7(-4.175,-2) 8(-4.175,-2.8) 17(4.175,-2.8) 18(4.175,-2) 19(4.175,-1.2) 20(4.175,-0.4) 21(4.175,0.4) 22(4.175,1.2) 23(4.175,2) 24(4.175,2.8)
  oval 0.55x1.65 smd: 9(-2.8,-4.175) 10(-2,-4.175) 11(-1.2,-4.175) 12(-0.4,-4.175) 13(0.4,-4.175) 14(1.2,-4.175) 15(2,-4.175) 16(2.8,-4.175) 25(2.8,4.175) 26(2,4.175) 27(1.2,4.175) 28(0.4,4.175) 29(-0.4,4.175) 30(-1.2,4.175) 31(-2,4.175) 32(-2.8,4.175)
  silkscreen extent -4.3,-2.95 2.95,3.75, body extent -3.5,-3.5 3.5,3.5, height 1.6
TI-DBV5_N [mm] "SOT23, 5-Leads, Body 2.9x1.6mm, Pitch 0.95mm, IPC Medium Density"
  rect 1.5x0.6 smd: 1(-1.15,0.95) 2(-1.15,0) 3(-1.15,-0.95) 4(1.15,-0.95) 5(1.15,0.95)
  silkscreen extent -1.27,1.68 -1.03,1.92, body extent -0.87,-1.52 0.87,1.53, height 1.45

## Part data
C1 C14: library part "Cap Pol", "Polar capacitor", ASiD Part Number=C-AS, Volte=35v
C2 C3 C4 C10 C11 C12 C13 C15 C16 C17 C18 C19 C20 C21 C22 C31 C32 C34 C35 C36 C37 C38 C39 C40 C41 C42 C57 C58: library part "Cap ceramic", "None polar capacitor", ASiD Part Number=C-AS, Volte=25v
C5 C6 C7 C8 C9 C23 C24 C25 C26 C27 C28 C29 C30 C33 C43 C53 C54 C55 C59: library part "Cap ceramic", "None polar capacitor", ASiD Part Number=C-AS, Volte=50v
C44 C49 C50 C51 C52: library part "Cap ceramic", "None polar capacitor", Volte=50v
C45 C46: library part "Cap ceramic", "None polar capacitor", Volte=16v
C47: library part "Cap Pol", "Polar capacitor", Volte=25v
C48: library part "Cap ceramic", "None polar capacitor", Volte=25v
C56: library part "Cap ceramic", "CAP-100Nf"
D1 D2 D3 D5 D6 D7: library part 1N4007, "1 Amp Diode", ASiD Part Number=1n4007-AS
D4: "Typical INFRARED GaAs LED", ASiD Part Number=LED-AS
D8: "Typical INFRARED GaAs LED"
D9: library part 1N4007, "1 Amp Diode"
JP1 JP2 JP3 P1 P2 P3 P4 P5 P6: "Header, 2-Pin", ASiD Part Number="Header 2-AS"
JTAG1: "Header, 5-Pin, Dual row"
L1: library part "INDUCTOR IRON", "Power Inductor 1uH", Manufacturer=-
L3: library part Inductor, "Inductor", Current=4.7A
Q2 Q3 Q4 Q5 Q6 Q7: "N-Channel OptiMOS 3 Power-Transistor, 60 V VDS, 50 A ID, -55 to 150 degC, PG-TDSON-8-1, Reel, Green", Manufacturer=Infineon, Supplier Part Number 1=726-BSC100N06LS3G
Q8: "N-Channel OptiMOS Small-Signal-Transistor, 60 V VDS, 0.3 A ID, -55 to 150 degC, PG-SOT23, Reel, Green", Manufacturer=Infineon, Supplier Part Number 1=6oGnorwKIcmhtwqcFeJ1owu1VFxg26S-d6kZGECfY84
Q9: "NPN Silicon AF Transistor, 80 V VCEO, 1000 mA IC, SOT223, Reel, Green", Manufacturer=Infineon
R1 R2 R3 R4 R5 R6 R7 R8 R9 R10 R11 R12 R13 R14 R15 R16 R17 R18 R19 R20 R21 R22 R23 R24 R25 R26 R27 R28 R29 R30 R31 R32 R33 R34 R35 R36 R37 R38 R39 R40 R41 R42 R66 R67: library part Res, "Standard resistor", ASiD Part Number=Res-AS
R55 R56 R57 R58 R59 R60: library part Res, "Standard resistor"
R61 R62 R63 R64 R65: library part Res, "resistor 1/4 wat"
S1 S2 S3 S4: "3mm Screw", ASiD Part Number=Screw-AS
sw1: library part "Tac switch", "small tac switch", ASiD Part Number="Tac switch-AS"
TP1 TP2: library part "Test Point", "Test point"
U1: "I2C Multi-Chemistry Battery Buck-Boost Charge Controller With System Power / Monitor and Processor Hot Monitor"
U2: "Adjustable Precision Shunt Regulator, 34 ppm / degC, 100 mA, 0 to 70 degC, 5-pin SOT-23 (DBV), Green (RoHS & no Sb/Br)", Manufacturer="Texas Instruments", Rating=Catalog, Supplier Part Number 1=296-15236-2-ND, Temp Coeff(Max)(ppm/ degree C)=92, Temp Coeff(Typ)(ppm/ degree C)=34
U3: "ARM Cortex-M0 32-bit MCU, 32 KB Flash, 4 KB Internal RAM, 26 I/Os, 32-pin LQFP, -40 to 85 degC, Tray", I/Os (High Current)=26, Operating Frequency(F) (Processor speed) (MHz)=48, Supplier Part Number 1=497-14046-ND, Supply Voltage(Vcc) min (V)=2.4
U4: "3A, 28V INPUT, STEP DOWN SWIFT™ DC/DC CONVERTER WITH ECO-MODE"
U5: "Low Drop Voltage Reg", ASiD Part Number=LM1117-AS
W1: "Jumper Wire", ASiD Part Number=Jumper-AS

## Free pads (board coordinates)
  oval 60x104 hole 39.37: 2(3084.25,4507.87) 3(2884.25,4507.87)

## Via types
v1: diameter 23.62, hole 11.81, Top Layer to Bottom Layer, 85 vias
v2: diameter 39.37, hole 19.68, Top Layer to Bottom Layer, 8 vias

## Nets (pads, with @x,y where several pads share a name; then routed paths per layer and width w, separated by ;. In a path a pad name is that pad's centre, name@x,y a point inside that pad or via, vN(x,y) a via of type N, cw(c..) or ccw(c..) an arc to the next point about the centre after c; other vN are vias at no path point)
3.3V: C53.2 C54.2 C55.2 C58.2 C59.2 JTAG1.1 R35.2 R61.1 R62.1 R63.1 R64.1 R66.1 U3.1 U3.5 U3.17 U5.2 | length 4971.5
  Top Layer w11.81: 1224.41,3023.62 U3.17
  Top Layer w16: C54.2 1198.82,2970.47 1224.41,2996.06 1224.41,3023.62 ; U3.5 v1(1318.9,3444.88) 1318.9,3490.16 C55.2 ; v1(1444.88,3444.88) U3.1 1510.83,3384.84 1533.47,3407.48 C53.2 ; v1(1476.38,2818.9) 1476.38,3000 1486.22,3009.84 R62.1
  Top Layer w30: v1(1169.29,3070.87) 1169.29,3023.62 1198.82,2994.09 1198.82,2970.47 ; v1(1488.19,3074.8) 1527.56,3035.43 ; R62.1 1527.56,3035.43 ; R64.1 R63.1 R61.1 1727.03,3056.43 1716.54,3066.93 1547.24,3066.93 1527.56,3047.24 1527.56,3035.43
  Top Layer w50: R35.2 2937.01,3220.47 3003.94,3153.54 3003.94,2877.97 3003.94,2798.59 R66.1 C59.2 C58.2
  Bottom Layer w16: v1(1476.38,2818.9) 1476.38,2702.76 JTAG1.1
  Bottom Layer w30: v1(1169.29,3070.87) 1169.29,3322.83 1291.34,3444.88 v1(1318.9,3444.88) v1(1444.88,3444.88) 1444.88,3118.11 v1(1488.19,3074.8) 1673.23,3074.8 1714.57,3116.14 2057.09,3116.14 2257.87,2915.35 2616.14,2915.35 2807.81,3107.02 2953.37,3107.02 3002.59,3107.02 U5.2@3051.8,3107.02
3.3VBQ: Q9.3 R9.1 R10.1 R20.2 R23.2 R25.2 R26.2 R28.2 R32.1 R35.1 R37.1 | length 5181.6
  Top Layer w16: R37.1 2244.15,3513.83 2244.15,3651.52 R32.1 ; Q9.3 2318.9,3362.2 v1(2326.77,3354.33) ; v1(2551.18,3354.33) 2935.04,3354.33 R35.1 ; v1(4177.17,4311.02) 4177.17,3787.4 4244.09,3720.47 v1(4244.09,3330.71)
  Top Layer w40: Q9.3 R25.2@2318.9,3653.54
  Top Layer w50: R32.1 R25.2@2318.9,3653.54 ; R23.2 R25.2 R20.2 R26.2 ; R35.1 R28.2@2937.01,3460.63
  Bottom Layer w16: v1(2326.77,3354.33) v1(2551.18,3354.33) 3153.54,3354.33 3346.46,3161.42 3988.19,3161.42 4157.48,3330.71 v1(4244.09,3330.71) ; v1(4177.17,4311.02) 4214.57,4348.42 R10.1 4438.98,4348.42 4448.82,4338.58 4448.82,3903.54 R9.1
5V: C45.2 C46.2 C57.2 D8.A L3.2 P6.1 R55.1 TP1.1 U5.3 | length 3082
  Top Layer w16: 3282.13,2354.41 3282.13,2734.41 3317.13,2769.41 3382.13,2769.41 3437.13,2824.41 D8.A
  Top Layer w50: v2(3164,2878.67) 3094.64,2878.67 U5.3 3093.94,2950.34 3108.16,2964.57 C57.2
  Top Layer w51.18: R55.1 L3.2@3374.72,2319.41
  Top Layer w62.99: C45.2 3738.13,2459.29 TP1.1@3738.13,2239.41
  Top Layer w118.11: P6.1 2487.36,2461.46 2649.61,2299.21 3352.3,2299.21 L3.2@3354.33,2301.24 ; L3.2 3694.61,2346.93
  Bottom Layer w50: v2(3164,2878.67) 3164,2492.13 3220.47,2435.66 v1(3220.47,2354.33)
ADC0: R41.2 R42.1 U3.6 | length 737.8
  Top Layer w11.81: v1(1237.46,3509.11) 1287.4,3459.16 U3.6
  Bottom Layer w20: v1(1237.46,3509.11) 1161.42,3585.15 1161.42,3858.27 1212.6,3909.45 R42.1 R41.2
ADC1: R39.2 R40.1 U3.7 | length 1194.5
  Top Layer w11.81: v1@1234.87,3467.15 1255.91,3446.12 U3.7
  Bottom Layer w20: v1(1232.28,3472.44) 1196.85,3472.44 1122.05,3547.24 1122.05,4271.65 1183.07,4332.68 R40.1 R39.2
AO_A: C1.+ C9.1 C10.2 C11.2 C12.2 C13.2 C14.+ C15.2 C16.2 C17.2 C18.2 C47.+ C48.2 C49.2 D7.A P3.2 Q1.1 Q1.3 Q4.5 Q4.6 Q4.7 Q4.8 R33.2 R56.1 U1.22 U4.2 | length 8549.8
  Top Layer w7.8: U1.22 3322.83,3913.39 v1(3338.58,3929.13) 3421.26,4011.81 3421.26,4224.41 3435.04,4238.19 C16.2 ; v1(3244.09,3842.52) 3246.06,3844.49 R33.2
  Top Layer w16: C16.2 C12.2 3566.93,4318.9
  Top Layer w20: D7.A 2509.84,2820.87 2393.7,2704.72 2393.7,2354.33 2594.49,2153.54 3917.32,2153.54 4092.38,2328.6 4092.38,2529.67
  Top Layer w23: Q4.5 3708.29,4322.83 3811.02,4322.83 3811.22,4322.64 3811.22,4289.57 ; Q1.3 3711.22,4300.59 ; Q1.1 3811.22,4289.57 ; C1.+ 3844.49,4590.55 C13.2 C18.2 3811.22,4289.57 ; C14.+ C14.+@4067.2,4808.78 ; P3.2@4067.2,4612.2 P3.2
  Top Layer w23.62: U4.2 4104.72,2869.41 R56.1@4107.13,2867.01
  Top Layer w50: C17.2 C10.2 C15.2 C11.2 3811.02,4557.09 C1.+@3844.49,4590.55
  Top Layer w51: 3551.18,4456.69 C10.2 ; 3641.73,4413.39 C15.2
  Top Layer w51.18: R56.1@4097.13,2867.01 4107.13,2867.01 C49.2 4244.84,2838.29 4316.13,2838.29 C48.2@4316.13,2847.29
  Top Layer w60: C1.+ P3.2@4067.2,4612.2
  Top Layer w65: C47.+@4007.13,2444.41 4092.38,2529.67 4316.13,2753.41 C48.2@4316.13,2838.29 ; C48.2 4375.85,2848.29 4409.45,2881.89 v1(4409.45,4574.8)
  Top Layer w80: P3.2@4067.2,4612.2 C14.+@4067.2,4808.78
  Bottom Layer w20: v1(3244.09,3842.52) 3291.34,3842.52 3338.58,3889.76 v1(3338.58,3929.13)
  Bottom Layer w65: P3.2 4379.57,4604.69 v1(4409.45,4574.8)
AO_B: C32.2 C33.1 Q1.5 Q1.6 Q1.7 Q1.8 R8.1 R11.1 | length 815.3
  Top Layer w11.81: C33.1@3470,3753.94 R8.1@3470,3807.09 ; C33.1@3480.32,3753.94 C33.1@3501.97,3732.28
  Top Layer w20: C33.1 3490.6,3664.91 R11.1
  Top Layer w30: Q1.7 3783.46,4011.81 v1(3783.46,4098.43)
  Top Layer w50: R8.1 3440.95,3892.98 3559.78,4011.81 3783.46,4011.81 3799.21,4011.81
  Bottom Layer w30: C32.2 v1(3783.46,4098.43)
AO_C: Q1.2 Q1.4 U1.21 | length 1027.8
  Top Layer w7.8: U1.21 3342.52,3897.64
  Top Layer w20: 3342.52,3897.64 3377.95,3897.64 3566.93,4086.61 3657.48,4086.61 ; Q1.4 3661.22,4090.35 3657.48,4086.61 ; Q1.2@3761.22,4204.72 3761.22,4135.13 3712.71,4086.61 3657.48,4086.61
BAT: C31.2 C33.2 D3.K D5.A P4.2 P5.2 R8.2 R12.1 | length 3525
  Top Layer w11.81: C33.2@3585,3733.25 R8.2@3585,3803.15
  Top Layer w20: D5.A 2763.78,2881.89 2854.33,2972.44 v1(2854.33,3031.5) ; C33.2@3576.77,3732.28 3576.77,3694.88 3614.17,3657.48 R12.1@3614.17,3647.64
  Top Layer w30: P5.2 4040.98,3722.8 3982.64,3722.8 3944.88,3685.04 3944.88,3429.13 4129.92,3244.09 v1(4177.17,3244.09)
  Top Layer w50: R8.2@3615.17,3829.71 R8.2@3624.05,3838.58 ; P5.2@4040.98,3722.8 3925.2,3838.58 D3.K 3877.95,3877.95 3877.95,4090.55 3939.33,4151.93 P4.2
  Top Layer w60: R8.2@3624.05,3838.58 D3.K
  Bottom Layer w20: v1(2854.33,3031.5) 3035.43,3031.5 3129.92,3125.98 4059.06,3125.98 v1(4177.17,3244.09)
CHG_OK: Q8.1 R26.1 U1.4 U3.3 | length 1896.6
  Top Layer w7.8: R26.1 2507.87,3834.65 2570.87,3897.64 U1.4
  Top Layer w11.81: U3.3 1381.89,3469.74 v1@1398.99,3486.84
  Top Layer w16: Q8.1 2230.31,3891.73 2240.16,3901.57 v1(2267.72,3901.57) 2357.91,3901.57 2399.61,3859.88 R26.1
  Bottom Layer w16: v1(1401.57,3492.13) 1488.19,3578.74 1944.88,3578.74 v1(2267.72,3901.57)
COMP1: C38.1 R22.1 U1.16 | length 589.6
  Top Layer w7.8: U1.16 3011.81,3791.34 v1(3039.37,3763.78)
  Top Layer w16: R22.1 3267.13,3620.08 v1(3286.12,3601.08) 3307.09,3580.12 C38.1
  Bottom Layer w16: v1(3039.37,3763.78) 3202.07,3601.08 v1(3286.12,3601.08)
EN_OTG: U1.5 U3.26 | length 1773.8
  Top Layer w7.8: v1(2543.31,3830.71) 2594.49,3881.89 U1.5
  Top Layer w11.81: U3.26 v1(1570.87,3141.73) ; v1(1696.85,3425.2) 1862.2,3590.55 v1(2216.54,3590.55)
  Bottom Layer w11.81: v1(1570.87,3141.73) 1570.87,3299.21 v1(1696.85,3425.2) ; v1(2216.54,3590.55) 2456.69,3830.71 v1(2543.31,3830.71)
GND: C23.2 C28.1 C30.2 C35.1 C36.2 C37.2 C38.2 C40.2 C41.1 C42.1 JP3.2 Q8.2 R27.1 R29.1 R31.1 R34.1 W1.1 | length 3386.7
  Top Layer w16: JP3.2@3405.51,3318.9 JP3.2 3415.36,3324.8 R27.1
  Top Layer w20: Q8.2 2155.51,3891.73 2206.69,3942.91 C30.2 2208.66,3978.35 v1(2208.66,4043.31) ; R29.1@2570.87,3474.41 2566.93,3470.47 2557.09,3470.47 2506.32,3521.24 2506.32,3566.93 2535.93,3596.54 2655.6,3596.54 2687.01,3627.95 C35.1 2681.1,3728.35 2629.92,3779.53 v1(2629.92,3807.09) ; C23.2 2683.07,3992.13 v1(2748.03,3992.13) ; R31.1 2846.46,3413.39 2854.33,3405.51 v1(2870.08,3405.51) ; C36.2@3125.98,3468.5 v1(3125.98,3405.51) 3139.76,3391.73 C40.2 C38.2 3344.49,3391.73 3389.76,3437.01 R27.1
  Top Layer w50: R29.1@2582.68,3470.47 C42.1 C41.1 R31.1 ; C28.1 2655.51,3976.38 C23.2 ; W1.1@3031.5,3379.92 3031.5,3468.5 C36.2@3125.98,3468.5
  Bottom Layer w20: v1(2208.66,4043.31) 2330.71,4165.35 2653.54,4165.35 2748.03,4070.87 v1(2748.03,3992.13) 2629.92,3874.02 v1(2629.92,3807.09) ; v1(2870.08,3405.51) v1(3125.98,3405.51) ; 3405.51,3549.21 3405.51,3322.83 JP3.2
ILIM_HIZ: C39.2 R18.1 R24.2 U1.6 | length 472.8
  Top Layer w7.8: C39.2@2590.55,3736.22 2590.55,3812.99 2608.27,3830.71 2675.2,3830.71 R18.1 ; R18.1@2687.01,3842.52 2710.63,3866.14 U1.6
  Top Layer w16: R24.2 C39.2
NetC2_2: C2.2 C3.2 C4.2 C19.2 C20.2 C21.2 D1.K D2.K R1.1 R2.1 R6.1 | length 1629.1
  Top Layer w11.81: R6.1@2331.71,4142.7 R1.1@2331.71,4207.66 ; R6.1@2343.52,4135.94 R6.1@2343.64,4135.83 ; R6.1@2343.52,4142.7 R6.1
  Top Layer w51: D2.K R2.1@1901.57,4229.35 ; D1.K 1884.83,4432.07 1884.83,4279.53 1886.8,4277.56 ; 1981.31,4235.22 1975.44,4229.35 1943.88,4229.35 ; R1.1@2271.65,4194.88 C4.2 C19.2 C2.2 1978.35,4194.88 1943.88,4229.35 ; R1.1@2275.59,4277.56 C21.2 C20.2 C3.2 1886.8,4277.56 ; 1886.8,4277.56 1901.57,4262.78 R2.1@1901.57,4229.35 ; R2.1@1901.57,4229.35 1943.88,4229.35
  Top Layer w62: 1981.31,4235.22 R1.1@2275.59,4235.22
NetC5_1: C5.1 C6.1 Q2.5 Q2.6 Q2.7 Q2.8 R1.2 R3.2 R7.1 | length 608.2
  Top Layer w11.81: R7.1@2448.82,4135.83 R1.2@2448.82,4207.66 ; R7.1@2453.64,4135.83 R7.1@2453.76,4135.94
  Top Layer w20: R7.1 R7.1@2453.64,4135.83 ; R7.1@2448.82,4135.83 R7.1@2453.64,4135.83 ; R3.2 R7.1@2453.64,4135.83
  Top Layer w50: C6.1@2460.04,4429.13 2460.04,4354.33 2602.36,4354.33 2622.05,4334.65
  Top Layer w80: R1.2@2484.25,4254.91 2656.48,4254.91
NetC7_1: C7.1 U1.30 | length 217.2
  Top Layer w7.8: C7.1@2862.2,4147.64 2883.86,4147.64 2933.07,4098.43 U1.30
NetC7_2: C7.2 L1.1 pad.3 Q2.1 Q2.2 Q2.3 Q3.5 Q3.6 Q3.7 Q3.8 R4.1 U1.32 | length 1347.3
  Top Layer w7.8: C7.2 2862.2,4043.31 2901.57,4003.94 U1.32
  Top Layer w25.5: Q2.3 2614.17,4531.5 2614.17,4543.31 ; Q2.2 2664.17,4532.68 ; Q2.1 2714.17,4529.92
  Top Layer w30: R4.1@2466.54,4531.5 2478.35,4543.31 2614.17,4543.31 ; 2614.17,4531.5 2625.98,4531.5 ; 2826.77,4409.45 2795.28,4377.95 2795.28,4102.17 2808.86,4088.58 C7.2
  Top Layer w100: 2653.54,4598.43 2787.4,4598.43 2826.77,4559.06 2826.77,4409.45
NetC8_1: C8.1 U1.25 | length 183.2
  Top Layer w7.8: U1.25 3011.81,3996.06 3019.67,4003.92 3074.8,4003.92 3100.41,4029.53 C8.1@3157.48,4029.53
NetC8_2: C8.2 L1.2 pad.2 Q4.1 Q4.2 Q4.3 Q5.5 Q5.6 Q5.7 Q5.8 R5.1 U1.23 | length 1630.6
  Top Layer w7.8: U1.23 3098.43,3929.13 v1(3111.22,3941.93) 3124.02,3954.72 C8.2@3157.48,3954.72
  Top Layer w16: C8.2@3157.48,3954.72 C8.2 R5.1@3251.97,3954.72
  Top Layer w22: 3236.22,4366.14 3288.78,4418.7
  Top Layer w25.5: 3393.7,4370.08 Q4.3 ; 3393.7,4420.08 Q4.2 ; Q5.5@3393.7,4470.08 Q4.1
  Top Layer w100: pad.2 3084.25,4375.59 3074.8,4366.14 3236.22,4366.14
  Bottom Layer w20: v1(3111.22,3941.93) 3109.25,3941.93 3080.53,3970.66 3080.53,4324.62 ; 3080.53,4324.62 3084.25,4328.35 pad.2 3080.53,4504.15 3080.53,4324.62
NetC22_2: C22.2 R2.2 | length 85.5
  Top Layer w16: R2.2@1773.59,4208.66 R2.2 ; R2.2@1773.59,4228.35 R2.2@1774.59,4229.35
  Top Layer w50: C22.2 R2.2@1773.59,4208.66
NetC24_2: C24.2 R4.2 | length 82.7
  Top Layer w30: C24.2 R4.2
NetC25_2: C25.2 R5.2 | length 90.6
  Top Layer w16: R5.2@3251.97,4029.53 C25.2@3342.52,4029.53
NetC26_1: C26.1 Q3.4 U1.29 | length 1122.2
  Top Layer w7.8: v1(2917.21,4207.66) 2948.93,4175.94 2948.93,3972.55 U1.29
  Top Layer w16: C26.1@2455.71,4725.39 Q3.4 2562.99,4726.57 v1(2562.99,4775.59)
  Bottom Layer w16: v1(2562.99,4775.59) 2795.28,4543.31 2795.28,4329.6 v1(2917.21,4207.66)
NetC27_1: C27.1 Q5.4 U1.26 | length 576.2
  Top Layer w7.8: U1.26 2996.06,4011.81 3007.87,4023.62 3027.56,4023.62
  Top Layer w16: 3027.56,4023.62 3030.22,4023.62 3160.14,4153.54 3350.39,4153.54 3392.52,4195.67 Q5.4
NetC28_2: C28.2 C29.2 R7.2 U1.2 | length 576.7
  Top Layer w7.87: C28.2@2509.84,3976.38 2509.84,3938.98 2519.69,3929.13 U1.2
  Top Layer w11.81: R7.2@2453.64,4061.02 2435.04,4042.43 C29.2 2509.84,3976.38 C28.2
NetC29_1: C29.1 C30.1 R6.2 U1.3 | length 740.6
  Top Layer w7.87: C29.1@2356.3,3976.38 2356.3,3931.1 2374.02,3913.39 U1.3
  Top Layer w11.81: C30.1 2356.3,3976.38 C29.1 2360.24,4044.42 R6.2@2343.64,4061.02
NetC36_1: C36.1 R19.2 | length 123
  Top Layer w16: R19.2 3114.17,3610.24 3125.98,3598.43 C36.1@3125.98,3553.15
NetC37_1: C37.1 R19.1 U1.17 | length 398.6
  Top Layer w7.8: U1.17 3082.68,3834.65 3114.17,3803.15 R19.1
  Top Layer w16: C37.1@3031.5,3553.15 3031.5,3594.49 3059.06,3622.05 3059.06,3736.22 3068.9,3746.06 R19.1
NetC39_1: C39.1 R24.1 | length 134.8
  Top Layer w16: R24.1 C39.1 ; C39.1 2596.46,3653.54 2610.24,3653.54 2604.33,3647.64 C39.1
NetC40_1: C40.1 R22.2 | length 78.7
  Top Layer w16: C40.1 R22.2
NetC41_2: C41.2 U1.9 | length 314.3
  Top Layer w7.8: C41.2@2755.91,3553.15 2755.91,3602.1 2827.03,3673.23 2827.03,3711.3 2901.57,3785.84 U1.9
NetC42_2: C42.2 R29.2 U1.8 | length 472
  Top Layer w7.8: R29.2@2574.8,3553.15 C42.2@2647.64,3553.15 ; C42.2 2669.08,3545.28 2811.43,3687.63 2811.43,3808.26 2837.82,3834.65 U1.8
NetC43_1: C43.1 R37.2 R38.1 U2.4 | length 254.6
  Top Layer w16: R37.2@2147.64,3511.81 2147.64,3413.39 2143.7,3409.45 2143.7,3352.36 2155.51,3340.55 C43.1 C43.1@2232.28,3340.55
NetC43_2: C43.2 Q9.1 R36.2 U2.3 | length 701
  Top Layer w16: U2.3 2155.51,3230.32 2190.94,3265.75 C43.2 2224.41,3192.91 2192.91,3161.42 R36.2
  Top Layer w30: C43.2 2226.38,3263.78 v1(2311.02,3263.78) ; v1(2500,3295.28) Q9.1
  Bottom Layer w30: v1(2311.02,3263.78) 2468.5,3263.78 v1(2500,3295.28)
NetC44_1: C44.1 U4.1 | length 151.8
  Top Layer w23.62: U4.1 4017.13,2819.41 4049.72,2786.81 C44.1
NetC44_2: C44.2 D9.K L3.1 U4.8 | length 1070.5
  Top Layer w23.62: 3662.13,2799.41 3682.13,2819.41 U4.8 ; C44.2 4164.72,2712.01 4182.13,2729.41 v2@4182.13,2749.41
  Top Layer w35: D9.K@3662.13,2688.74 v2(3662.13,2752.41) 3662.13,2799.41
  Top Layer w118.11: L3.1 D9.K@3688.98,2661.89
  Bottom Layer w23.62: v2(3662.13,2752.41) v2@4179.13,2752.41 ; v2@4182.13,2749.41 v2@4179.13,2752.41 ; v2(4182.13,2752.41) v2@4179.13,2752.41
NetC50_1: C50.1 R60.1 | length 88.6
  Top Layer w23.62: R60.1 3627.13,3062.01 C50.1
NetC50_2: C50.2 C51.2 U4.6 | length 210.5
  Top Layer w23.62: C51.2 C50.2 3669.72,2902.01 3687.13,2919.41 U4.6
NetC52_2: C52.2 U4.4 | length 213.3
  Top Layer w23.62: U4.4 4022.13,2969.41 4024.82,2972.1 4024.82,2976.44 4037.13,2988.74 4037.13,3049.41 4022.13,3064.41 C52.2
NetD4_A: D4.A R32.2 | length 181.3
  Top Layer w16: D4.A 2075.74,3691.98 2114.17,3653.54 R32.2
NetD4_K: D4.K Q8.3 | length 148.2
  Top Layer w16: D4.K 2096.46,3840.55 2171.26,3765.75 Q8.3
NetD5_K: D5.K D6.K D7.K Q9.2 Q9.4 R36.1 | length 887.2
  Top Layer w30: R36.1 2242.13,3025.59 2275.59,3059.06 2346.46,3059.06 2350.39,3055.12 2413.39,3055.12 ; Q9.2 Q9.4 2413.39,3169.29 2413.39,3055.12 ; D5.K 2413.39,3055.12
NetD8_K: D8.K R57.1 | length 95
  Top Layer w23.62: R57.1 D8.K
NetJP1_1: JP1.1 R16.1 R21.2 | length 197.3
  Top Layer w16: JP1.1 3627.56,3367.72 3647.64,3387.8 R21.2 R16.1
NetJP1_2: JP1.2 JP2.2 JP3.1 R21.1 R27.2 U1.18 | length 1276.2
  Top Layer w7.8: U1.18 3098.43,3850.39 3490.16,3458.66 R27.2
  Top Layer w16: JP3.1 JP2.2 ; 3527.56,3224.41 JP1.2 3527.56,3358.27 3490.16,3395.67 R27.2 R21.1
NetJP2_1: JP2.1 R17.1 | length 220.8
  Top Layer w16: R17.1 3726.38,3301.18 3744.09,3283.46 3822.83,3283.46 3840.16,3266.14 JP2.1
NetP4_1: P4.1 Q6.5 Q6.6 Q6.7 Q6.8 R13.1 | length 342.7
  Bottom Layer w50: R13.1@3940.94,4001.97 3990.98,3951.93 P4.1 Q6.7@4262.95,3951.93
NetP5_1: P5.1 Q7.5 Q7.6 Q7.7 Q7.8 R14.1 | length 389.4
  Bottom Layer w50: R14.1@3944.88,3588.58 4010.67,3522.8 4082.6,3522.8 4091.3,3531.5 4275.59,3531.5 4295.28,3551.18
NetQ2_4: Q2.4 U1.31 | length 697.2
  Top Layer w7.8: v1(2909.45,4031.5) 2909.45,4018.12 2917.21,4010.36 2917.21,3972.55 U1.31
  Top Layer w16: v1(2523.62,4429.13) Q2.4
  Bottom Layer w16: v1(2523.62,4429.13) 2523.62,4354.33 2846.46,4031.5 v1(2909.45,4031.5)
NetQ4_4: Q4.4 U1.24 | length 658.4
  Top Layer w7.8: U1.24 3078.74,3944.88 v1(3114.17,3980.32)
  Top Layer w16: v1(3433.07,4295.28) 3437.01,4295.28 3460.43,4318.7 Q4.4@3471.46,4318.7
  Bottom Layer w16: v1(3114.17,3980.32) 3240.16,3980.32 3275.59,4015.75 3275.59,4137.8 v1(3433.07,4295.28)
NetR11_2: R11.2 U1.20 | length 596.5
  Top Layer w7.8: U1.20 3122.05,3881.89 3431.1,3572.83 R11.2
NetR12_2: R12.2 U1.19 | length 746.5
  Top Layer w7.8: U1.19 3111.4,3866.14 3449.98,3527.56 3590.55,3527.56 3614.17,3551.18 R12.2@3614.17,3572.83
NetR20_1: R20.1 U1.11 | length 724.9
  Top Layer w7.8: v1(2877.95,3704.72) 2877.95,3710.41 2933.07,3765.53 U1.11
  Top Layer w16: R20.1 2421.26,3744.09 v1(2464.57,3787.4)
  Bottom Layer w11.81: v1(2464.57,3787.4) 2614.17,3637.8 2834.53,3637.8 2877.95,3681.21 v1(2877.95,3704.72)
NetR28_1: R28.1 R30.1 U1.15 | length 304.5
  Top Layer w7.8: U1.15 2996.06,3767.72 3027.56,3736.22 3027.56,3687.01 R30.1@3005.91,3665.35
  Top Layer w16: R28.1@2937.01,3553.15 2937.01,3570.87 3005.91,3639.76 R30.1@3005.91,3665.35
NetR30_2: R30.2 R33.1 R34.2 U1.14 | length 794.9
  Top Layer w7.8: R30.2@2931.1,3665.35 R30.2@2931.1,3665.57 ; R30.2@2931.1,3671.26 R30.2@2931.1,3665.57 ; R30.2@2934.93,3669.4 R30.2@2931.1,3665.57 ; R30.2 2938.98,3669.08 3000,3730.1 2980.31,3749.78 U1.14 ; R33.1 3314.96,3728.35 v1(3334.65,3708.66)
  Bottom Layer w16: v1(3000,3728.35) 3000,3773 3018.39,3791.39 3222.52,3791.39 3297.55,3716.36 3378.13,3716.36 3409.45,3685.04 R34.2
NetR31_2: R31.2 U1.10 | length 283.3
  Top Layer w7.8: R31.2@2846.46,3553.15 2846.46,3708.66 2917.32,3779.53 U1.10
NetR55_2: R55.2 R58.1 U4.5 | length 866.1
  Top Layer w20: U4.5@3697.13,2969.41 U4.5
  Bottom Layer w20: v2(3492.13,2224.41) 3492.13,2769.41 v2(3692.13,2969.41)
NetR56_2: R56.2 R59.1 U4.3 | length 206.3
  Top Layer w23.62: U4.3 4027.13,2919.41 4049.53,2941.81 4074.13,2941.81 4074.13,2979.41 4097.13,3002.41 R59.1
NetR66_2: R66.2 R67.1 U5.1 | length 170.2
  Top Layer w25: R67.1@2846.46,2858.27 2894.24,2858.27 U5.1 U5.1@2914,2877.9
  Top Layer w50: R66.2 U5.1@2914,2877.9
PACK1: Q7.4 R9.2 U3.21 | length 4962.3
  Top Layer w11.81: v1(1350.39,2964.57) U3.21
  Bottom Layer w12: v1(1350.39,2964.57) 1350.39,2614.17 1803.26,2161.3 3531.82,2161.3 3945.21,2574.69 4146,2574.69 4413.39,2842.08 4413.39,3688.98 4389.76,3712.6
  Bottom Layer w25: Q7.4 4370.28,3712.8 4389.76,3732.28 ; 4389.76,3712.6 4389.76,3732.28 ; R9.2 4389.76,3732.28
PACK2: Q6.4 R10.2 U3.22 | length 5583.2
  Top Layer w11.81: v1(1381.89,2984.25) U3.22
  Top Layer w12: v1(4161.42,3629.92) 4192.91,3598.43 4192.91,3307.09 v1(4232.28,3267.72)
  Bottom Layer w12: v1(1381.89,2984.25) 1381.89,2641.73 1842.52,2181.1 3523.62,2181.1 3937.01,2594.49 4137.8,2594.49 4311.02,2767.72 4311.02,3188.98 v1(4232.28,3267.72) ; v1(4161.42,3629.92) 4177.17,3645.67 4177.17,3822.83 4248.03,3893.7 4401.57,3893.7 4413.39,3905.51 4413.39,4149.61 4400.59,4162.4 Q6.4
  Bottom Layer w25: Q6.4 4370.28,4204.92 4389.76,4224.41 R10.2
PGND: C1.- C2.1 C3.1 C4.1 C5.2 C6.2 C9.2 C10.1 C11.1 C12.1 C13.1 C14.- C15.1 C16.1 C17.1 C18.1 C19.1 C20.1 C21.1 C22.1 C24.1 C25.1 C26.2 C27.2 C31.1 C32.1 C34.2 C45.1 C46.1 C47.- C48.1 C49.1 C51.1 C52.1 C53.1 C54.1 C55.1 C56.1 C57.1 C58.1 C59.1 D3.A D9.A JTAG1.3 JTAG1.5 P1.2 P2.2 P3.1 P6.2 Q3.1 Q3.2 Q3.3 Q5.1 Q5.2 Q5.3 Q6.1 Q6.2 Q6.3 Q7.1 Q7.2 Q7.3 R13.2 R14.2 R38.2 R40.2 R42.2 R57.2 R58.2 R59.2 R60.2 R65.2 R67.2 sw1.2 TP2.1 U1.27 U1.33 U2.5 U3.16 U3.31 U3.32 U4.7 W1.2 | length 27929.4
  Top Layer w7.8: U1.33@2980.31,3913.39 U1.27
  Top Layer w16: C54.1@1124.02,2960.63 v1@1124.02,3039.37 ; v1(1124.71,3040.07) v1@1124.02,3039.37 ; U3.31 1539.37,3299.21 C53.1@1570.87,3330.71 ; C53.1 1572.84,3332.68 C53.1@1570.87,3330.71 ; R65.2 1667.32,3009.84 1679.74,2997.43 1679.74,2683.68 1646.85,2650.79 JTAG1.3 ; 1647.64,3320.87 1708.66,3259.84 sw1.2 ; JTAG1.5 1792.52,2586.61 2000,2586.61 2062.99,2649.61 2062.99,3000 2053.15,3009.84 C56.1 ; v1@1124.02,3039.37 1124.02,3096.46 1137.8,3110.24 U3.16 1220.47,3110.24 1440.94,3330.71 U3.32 C53.1@1570.87,3330.71
  Top Layer w20: R58.2 3642.13,2224.41 3683.68,2182.86 3820.57,2182.86 3842.13,2204.41 TP2.1@3842.13,2239.41
  Top Layer w23.62: U4.7@3735.39,2869.41 U4.7@3827.13,2869.41
  Top Layer w25: P2.2 1425.28,3779.61 1326.77,3681.1 C55.1 1620.08,3572.83 1664.74,3528.17 1664.74,3321.48 1665.35,3320.87 ; C53.1 1588.58,3330.71 1598.42,3320.87 1647.64,3320.87 1665.35,3320.87 ; R38.2@2072.83,3413.39 2068.9,3409.45 U2.5 1665.35,3320.87 ; C24.1@2234.25,4531.5 2234.25,4358.27 2240.16,4352.36 ; 2240.16,4716.54 C26.2 ; 2610.24,4830.71 2614.17,4826.77 Q3.3 ; Q3.2 2664.17,4825.59 2669.29,4830.71 3370.08,4830.71 3460.63,4830.71 3551.18,4830.71 3641.73,4830.71 C1.-@3826.77,4830.71 ; P6.2 2690.66,2599.15 C58.1 C59.1 2849.67,2689.7 2826.77,2712.6 R67.2 ; Q3.1 2714.17,4825.59 ; C34.2 3070.87,4163.39 C27.2@3086.61,4179.13 ; C34.2@3019.68,4165.35 v1(3019.68,4220.47) ; C27.2 C27.2@3086.61,4179.13 ; v1(3145.67,4238.19) 3104.33,4196.85 ; v1(3187.01,4104.33) C25.1@3342.52,4104.33 ; Q5.1 3242.52,4199.21 3240.16,4196.85 ; Q5.2 3292.52,4203.54 3299.21,4196.85 ; Q5.3 3342.52,4208.66 3330.71,4196.85 3299.21,4196.85 ; C17.1 C10.1 C15.1 C11.1 ; v1(3503.94,4098.43) 3476.38,4125.98 C16.1 C12.1 ; v1(3708.66,3645.67) 3708.66,3704.72 ; C31.1 3708.66,3704.72 ; C18.1 C13.1 ; R59.2 4097.13,3198.15 3880.15,3415.13 3880.15,3564.73 3838.58,3606.3 D3.A 3748.03,3665.35 3708.66,3704.72 ; v1(4220.28,3791.14) v1(4220.28,4263.58) 4220.28,4404.69 ; v1(4270.28,3791.14) v1(4270.28,4263.58) 4270.28,4447.64 ; 4312.99,4517.71 4320.28,4510.43 v1(4320.28,4263.58) v1(4320.28,3791.14) ; C27.2@3086.61,4179.13 3104.33,4196.85 ; 3104.33,4196.85 3240.16,4196.85 ; 3240.16,4196.85 3299.21,4196.85
  Top Layer w50: P1.2 1501.69,4208.66 C22.1 ; v1@2043.31,4031.5 2043.31,4120.08 ; v1(2043.31,4440.94) 2043.31,4352.36 C20.1 C21.1 2240.16,4352.36 2385.24,4352.36 C6.2@2385.24,4429.13 ; C24.1@2234.25,4531.5 C24.1 2234.25,4765.75 2314.96,4846.46 3366.14,4846.46 ; W1.2 3135.83,3281.5 3179.75,3237.57 3179.75,3070.87 ; C17.1 3370.08,4830.71 3370.08,4842.52 3366.14,4846.46 ; C9.2 3460.63,4830.71 3460.63,4842.52 3464.57,4846.46 ; C10.1 3551.18,4830.71 3551.18,4837.86 3559.78,4846.46 ; C15.1 3641.73,4830.71 3641.73,4842.52 3637.8,4846.46 ; C11.1 3732.28,4818.9 ; C1.-@3836.62,4846.46 3637.8,4846.46 ; C1.- 3923.23,4860.23 3961.93,4898.94 4225.07,4898.94 C14.- 4312.99,4517.71 4312.99,4490.35 4270.28,4447.64 4227.32,4404.69 4220.28,4404.69 P3.1 3927.99,4404.69 C13.1 ; 3366.14,4846.46 3464.57,4846.46 ; 3464.57,4846.46 3559.78,4846.46 ; 3559.78,4846.46 3637.8,4846.46
  Top Layer w51: 2047.24,4116.14 2043.31,4120.08 C19.1 C4.1 2240.16,4120.08
  Top Layer w51.18: 3179.75,3070.87 3186.21,3064.41 v2(3486.13,3064.41) 3532.13,3018.41 C51.1 ; v2(3342.13,2844.41) R57.2 ; R60.2 3699.8,3064.69 v2(3797.13,3064.69) 3894.45,3064.69 C52.1 3894.72,3047.01 3852.13,3004.41 U4.7@3852.13,2894.41 ; R59.2 4213.13,3098.81 ; C49.1 4216.13,3095.81 4213.13,3098.81 ; v1(4240.16,3173.23) 4240.16,3102.75 4244.09,3098.81 ; C48.1 4317.13,3086.81 4305.13,3098.81 4244.09,3098.81 ; 4213.13,3098.81 4244.09,3098.81
  Top Layer w62.99: TP2.1 3848.13,2344.41 3848.13,2710.41 3852.13,2714.41
  Top Layer w65: C46.1@3847.24,2344.41 3848.13,2344.41 C47.-@4007.13,2344.41
  Top Layer w110.24: U4.7@3852.13,2894.41 3852.13,2714.41 3922.13,2644.41 D9.A
  Bottom Layer w16: v1(1124.71,3040.07) 1396.94,3040.07 1413.39,3023.62 1413.39,2893.7 1436.96,2870.13 1543.26,2870.13 1578.74,2834.65 1578.74,2700.39 JTAG1.3 JTAG1.5
  Bottom Layer w20: v1(2935.04,3868.11) v1(2978.35,3868.11) 3194.88,3868.11 3425.2,4098.43 v1(3503.94,4098.43)
  Bottom Layer w25: R40.2 1301.18,4257.87 1328.39,4285.08 P1.2 ; R42.2 1407.91,3834.65 P2.2 ; P6.2 2687.36,2833.49 2822.38,2968.5 3342.13,2968.5 ; v1(2935.04,3911.42) v1(2978.35,3911.42) 3019.68,3952.76 v1(3019.68,4220.47) ; v1(3145.67,4238.19) 3238.19,4238.19 ; v1(3187.01,4104.33) 3187.01,4187.01 3238.19,4238.19 ; v1(3503.94,4098.43) 3566.93,4098.43 ; v1(3708.66,3645.67) 3708.66,3704.72 ; R14.2 3750,3663.39 3708.66,3704.72 ; P3.1 3999.17,4404.69 3940.94,4346.46 3940.94,4076.77 R13.2 3875.98,4076.77 3807.09,4007.87 3643.7,4007.87 ; Q7.1 v1(4220.28,3791.14) ; Q6.1 v1(4220.28,4263.58) ; Q7.2 v1(4270.28,3791.14) ; Q6.2 v1(4270.28,4263.58) ; Q7.3 v1(4320.28,3791.14) ; Q6.3 v1(4320.28,4263.58) ; 3238.19,4238.19 3346.46,4346.46 3496.06,4346.46 3566.93,4275.59 3566.93,4098.43 ; 3566.93,4098.43 C32.1 3643.7,4007.87 ; 3643.7,4007.87 3643.7,3769.68 3708.66,3704.72
  Bottom Layer w50: v1(2043.31,4035.43) 2043.31,4291.34 v1(2043.31,4440.94)
  Bottom Layer w51: P2.2 1859.88,3852.01 v1(2043.31,4035.43) ; P1.2 2037.05,4285.08 2043.31,4291.34
  Bottom Layer w51.18: v2(3342.13,2844.41) 3342.13,2968.5 3342.13,3004.41 3402.4,3064.69 v2(3797.13,3064.69) 4131.61,3064.69 v1(4240.16,3173.23)
REGN: C34.1 R15.1 U1.28 | length 466.4
  Top Layer w7.8: U1.28 2964.57,4019.68 2996.06,4051.18 C34.1@2996.06,4068.9
  Bottom Layer w20: R15.1 2744.09,3862.2 2858.27,3976.38 2933.07,3976.38 2972.44,4015.75 v1(2972.44,4031.5)
RST: C56.2 JTAG1.10 R64.2 sw1.1 U3.4 | length 1593.1
  Top Layer w11.81: v1(1350.39,3324.8) U3.4 ; v1(1846.46,3078.74) 1901.57,3133.86 sw1.1 ; JTAG1.10 1928.35,2927.95 R64.2 C56.2
  Bottom Layer w11.81: v1(1350.39,3324.8) 1350.39,3157.48 1461.78,3046.1 1846.46,3046.1 ; v1(1846.46,3078.74) 1846.46,3046.1 ; JTAG1.10 1928.35,3003.94 1886.19,3046.1 1846.46,3046.1
SCL: R23.1 U1.13 U3.29 | length 1860.1
  Top Layer w7.8: v1(2200.79,3401.57) 2255.89,3401.57 v1@2263.77,3409.45 ; v1(2263.78,3401.57) v1@2263.78,3409.44 ; v1(2964.57,3732.28) U1.13
  Top Layer w11.81: U3.29 v1(1653.54,3236.22)
  Top Layer w16: R23.1 2407.48,3555.12 v1(2464.57,3555.12)
  Bottom Layer w11.81: v1(1653.54,3236.22) 2035.43,3236.22 v1(2200.79,3401.57) ; v1(2263.78,3401.57) 2311.02,3401.57 v1(2464.57,3555.12) 2847.08,3555.12 2964.57,3672.61 v1(2964.57,3732.28)
SDA: R25.1 U1.12 U3.30 | length 1851.9
  Top Layer w7.8: v1@2196.85,3444.88 v1(2200.79,3440.94) v1(2267.72,3440.94) ; R25.1 2462.6,3590.55 v1(2484.25,3590.55) ; v1(2925.2,3724.41) 2925.2,3728.35 2948.82,3751.97 U1.12
  Top Layer w11.81: U3.30 v1(1618.11,3267.72)
  Bottom Layer w11.81: v1(1618.11,3267.72) 1909.45,3267.72 2082.68,3440.94 v1(2200.79,3440.94) ; v1(2267.72,3440.94) 2287.4,3440.94 2437.01,3590.55 v1(2484.25,3590.55) 2838.81,3590.55 2925.2,3676.94 v1(2925.2,3724.41)
SWCLK: JTAG1.4 R65.1 U3.24 | length 642.1
  Top Layer w11.81: v1(1444.88,2984.25) U3.24 ; R65.1 1628.35,2933.99 JTAG1.4
  Bottom Layer w11.81: v1(1444.88,2984.25) 1574.8,2984.25 1628.35,2930.71 JTAG1.4
SWDIO: JTAG1.2 R62.2 U3.23 | length 584.6
  Top Layer w11.81: U3.23 1413.39,2783.46 1445.28,2751.57 JTAG1.2@1527.56,2751.57 ; R62.2 JTAG1.2@1527.56,2751.57 ; JTAG1.2 JTAG1.2@1527.56,2751.57
SWO: JTAG1.6 R61.2 | length 184.8
  Top Layer w11.81: R61.2 1728.35,2933.73 JTAG1.6
TDI: JTAG1.8 R63.2 | length 184.9
  Top Layer w11.81: R63.2 1828.35,2933.46 JTAG1.8
VADC_0: D1.A P1.1 R39.1 | length 375.4
  Top Layer w100: P1.1 1461.54,4448.82 D1.A
  Bottom Layer w20: R39.1 1420.2,4490.16 P1.1
VADC_1: D2.A P2.1 R41.1 | length 364.5
  Top Layer w100: P2.1 1461.54,4015.75 D2.A
  Bottom Layer w20: R41.1 1408.39,4068.9 P2.1
VBUS: C23.1 D6.A R3.1 U1.1 | length 1925.6
  Top Layer w7.8: C23.1@2665.36,4061.02 C23.1 2729.78,4072.83 2857.73,3944.88 U1.1
  Top Layer w16: D6.A v1(2334.65,2964.57) ; R3.1 2622.05,4061.02 ; v1(2622.05,4125.98) 2622.05,4061.02 ; C23.1@2665.36,4061.02 2622.05,4061.02
  Bottom Layer w16: v1(2334.65,2964.57) 2334.65,3122.1 2236.17,3220.58 2236.17,3523.62 2188.92,3570.87 2188.92,3614.12 2622.05,4047.24 v1(2622.05,4125.98)
VDDA: C35.2 R15.2 R16.2 R17.2 R18.2 U1.7 | length 1730.2
  Top Layer w7.8: R18.2 2791.34,3818.9 2822.83,3850.39 U1.7
  Top Layer w16: v1(3799.21,3511.81) 3801.18,3509.84 R16.2 R17.2
  Top Layer w20: v1(2759.84,3669.29) 2759.84,3726.38 C35.2 R18.2
  Bottom Layer w7.8: R15.2 R15.2@2759.84,3722.44
  Bottom Layer w16: R15.2 2883.86,3738.19 2960.86,3815.19 3232.38,3815.19 3232.66,3814.91 3255.53,3814.91 3255.81,3815.19 3267.49,3815.19 3283.46,3799.21 3448.82,3799.21 3736.22,3511.81 v1(3799.21,3511.81)
  Bottom Layer w20: v1(2759.84,3669.29) R15.2@2759.84,3722.44
pads on no net: JTAG1.7 JTAG1.9 S1.0 S2.0 S3.0 S4.0 U2.1 U2.2 U3.2 U3.8 U3.9 U3.10 U3.11 U3.12 U3.13 U3.14 U3.15 U3.18 U3.19 U3.20 U3.25 U3.27 U3.28

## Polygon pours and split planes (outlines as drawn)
PGND on Top Layer "Top_PGND" (solid, remove dead copper, pour order 4): 1003.94,2118.11 4476.38,2118.11 4476.38,4948.82 1003.94,4948.82
PGND on Bottom Layer "Bot_PGND" (solid, remove dead copper, pour order 5): 1003.94,2118.11 4476.38,2118.11 4476.38,4948.82 1003.94,4948.82

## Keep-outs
Keep-Out Layer:
  the board outline again, w20

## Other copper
Top Layer:
  rectangle net AO_A: 3801.18,4504.17 4161.42,4664.09
  rectangle net NetC5_1: 2440.94,4183.07 2582.68,4291.34
  rectangle net NetC5_1: 2546.65,4181.1 2761.81,4385.83
  rectangle net NetC7_2: 2602.36,4401.57 2818.9,4612.2
  rectangle net AO_A: 3539.37,4322.83 3844.49,4566.93
  rectangle net NetC8_2: 3082.68,4311.02 3410.04,4505.91
  rectangle net NetC8_2: 3000,4248.03 3110.24,4409.45
  rectangle net NetC7_2: 2779.53,4244.09 2938.98,4413.39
